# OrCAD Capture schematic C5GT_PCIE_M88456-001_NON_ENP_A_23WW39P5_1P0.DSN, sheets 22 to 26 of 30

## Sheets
22 PWR - Cycone V GT: size B
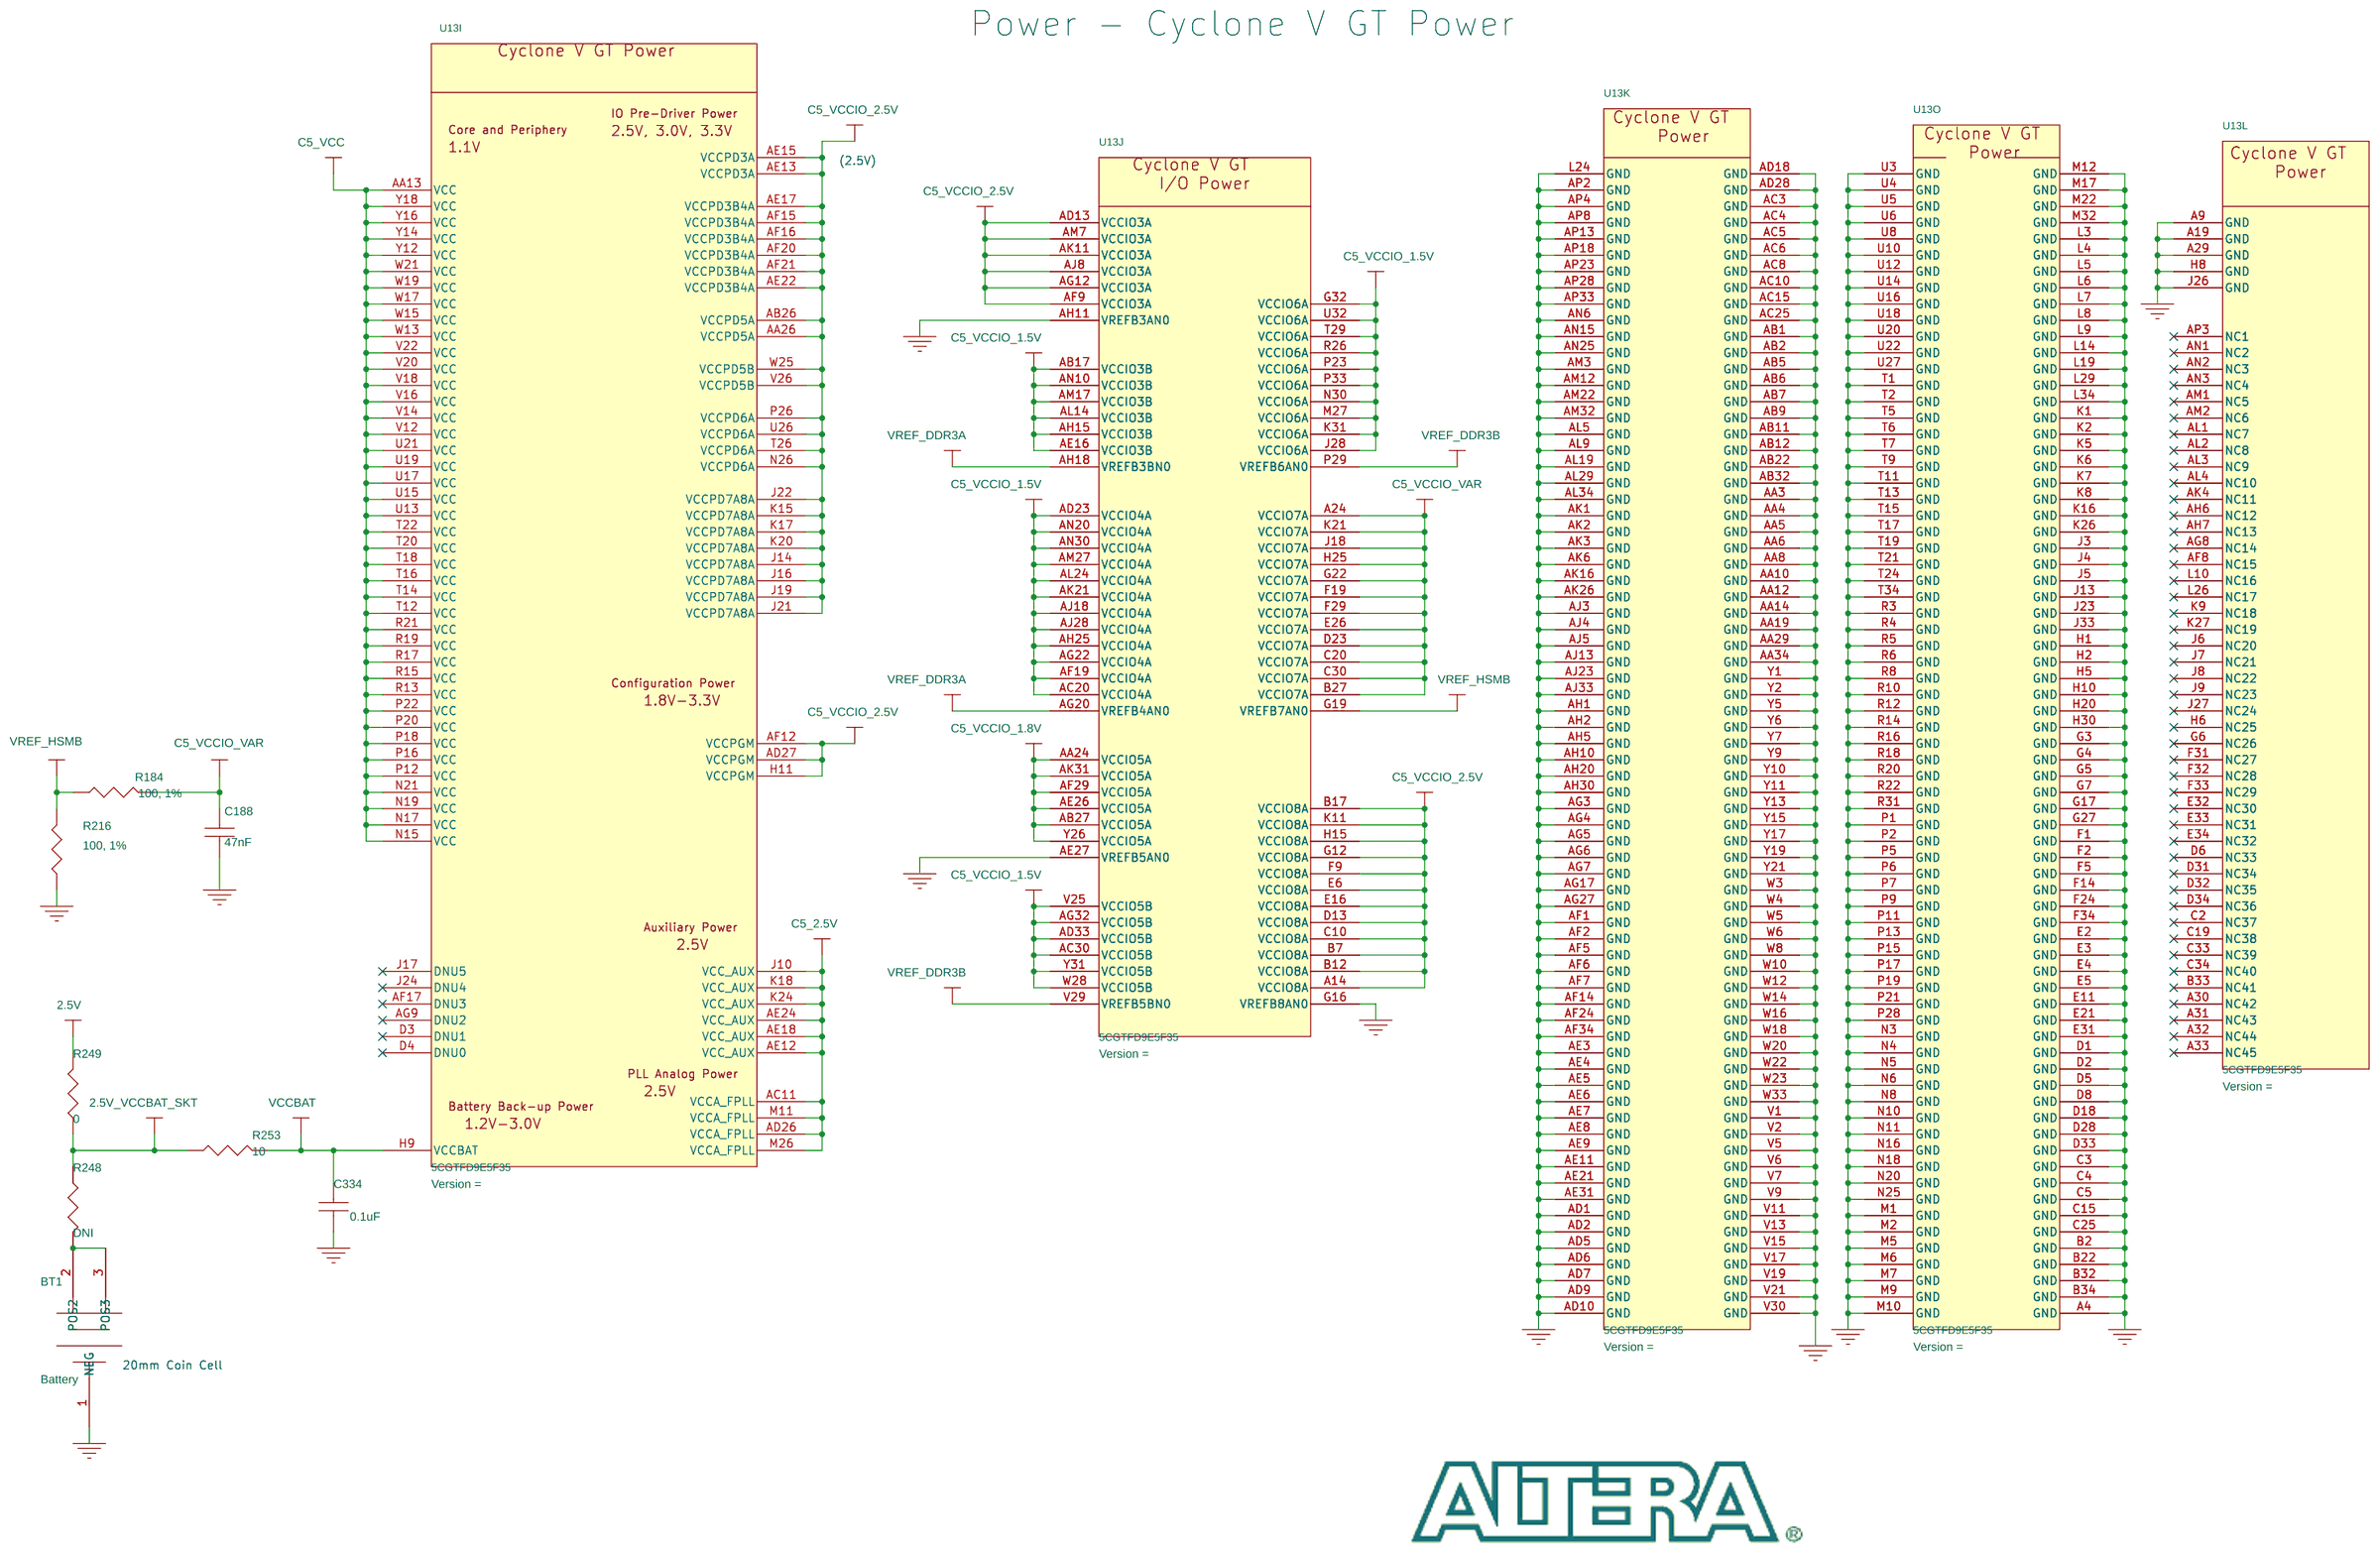
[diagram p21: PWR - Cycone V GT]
23 Power 1 - DCin to 12V,3.3V: size B
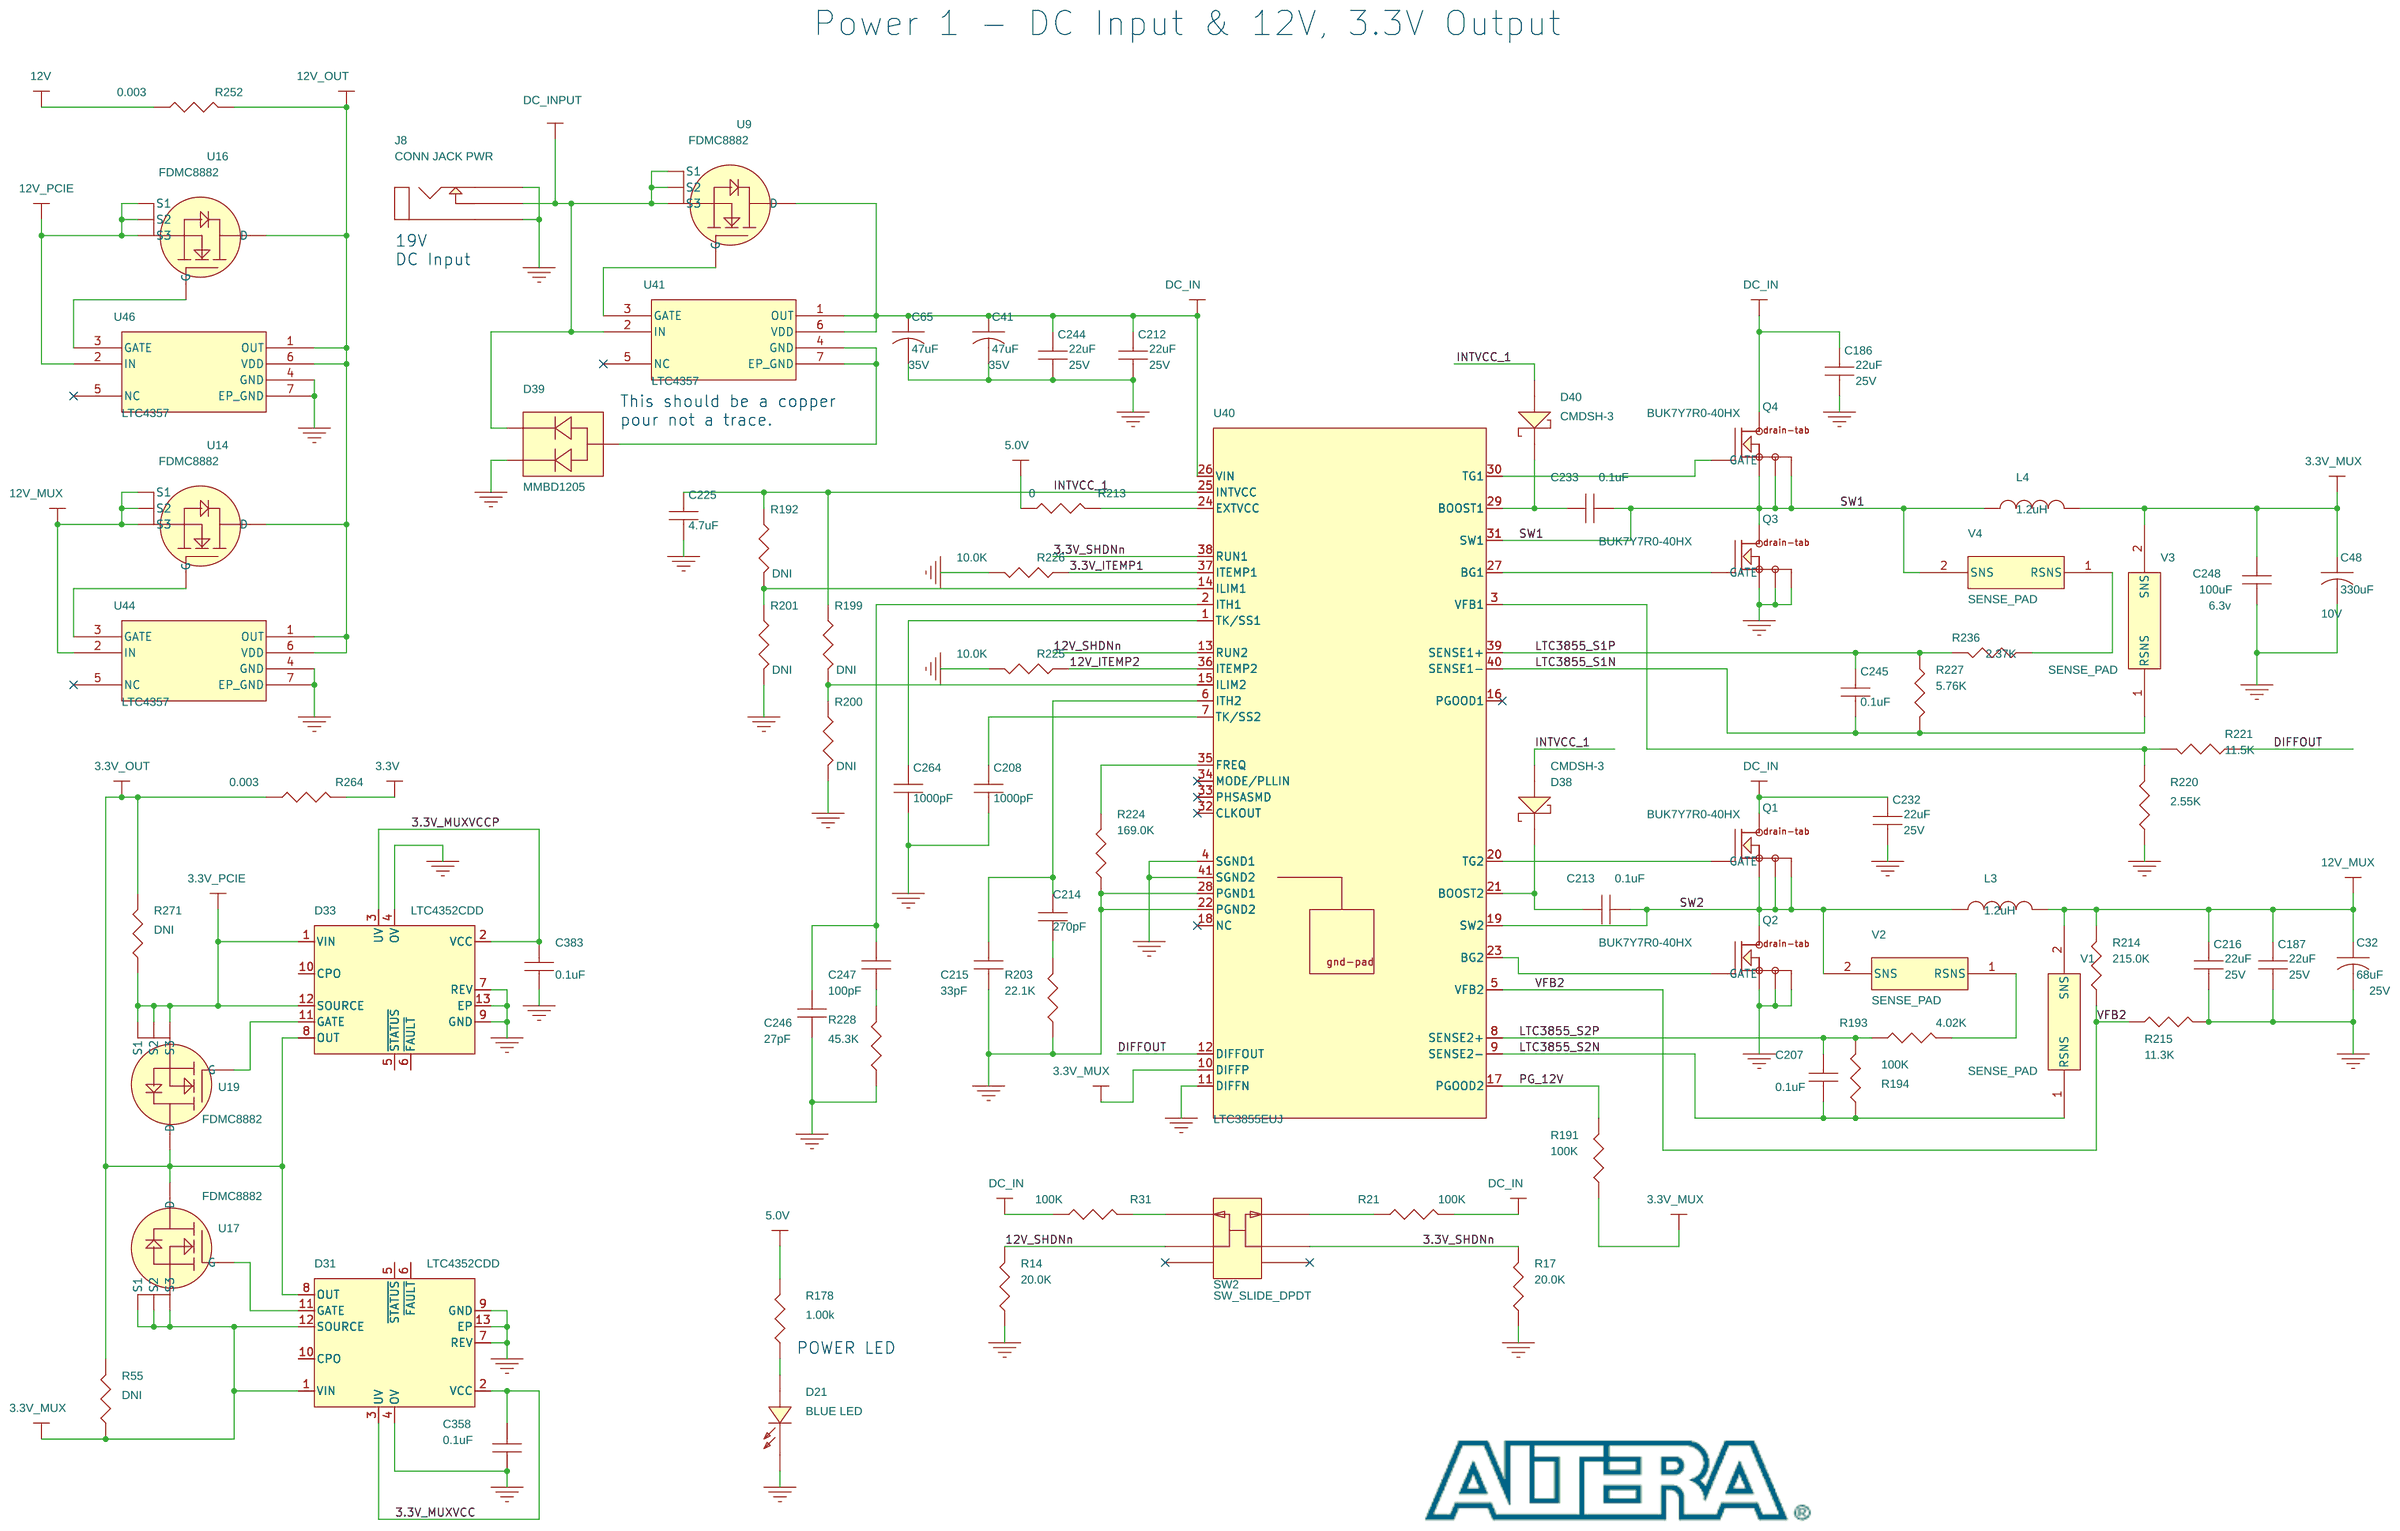
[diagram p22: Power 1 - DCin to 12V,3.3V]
24 Power 2 - 1.1V (C5_VCC): size B
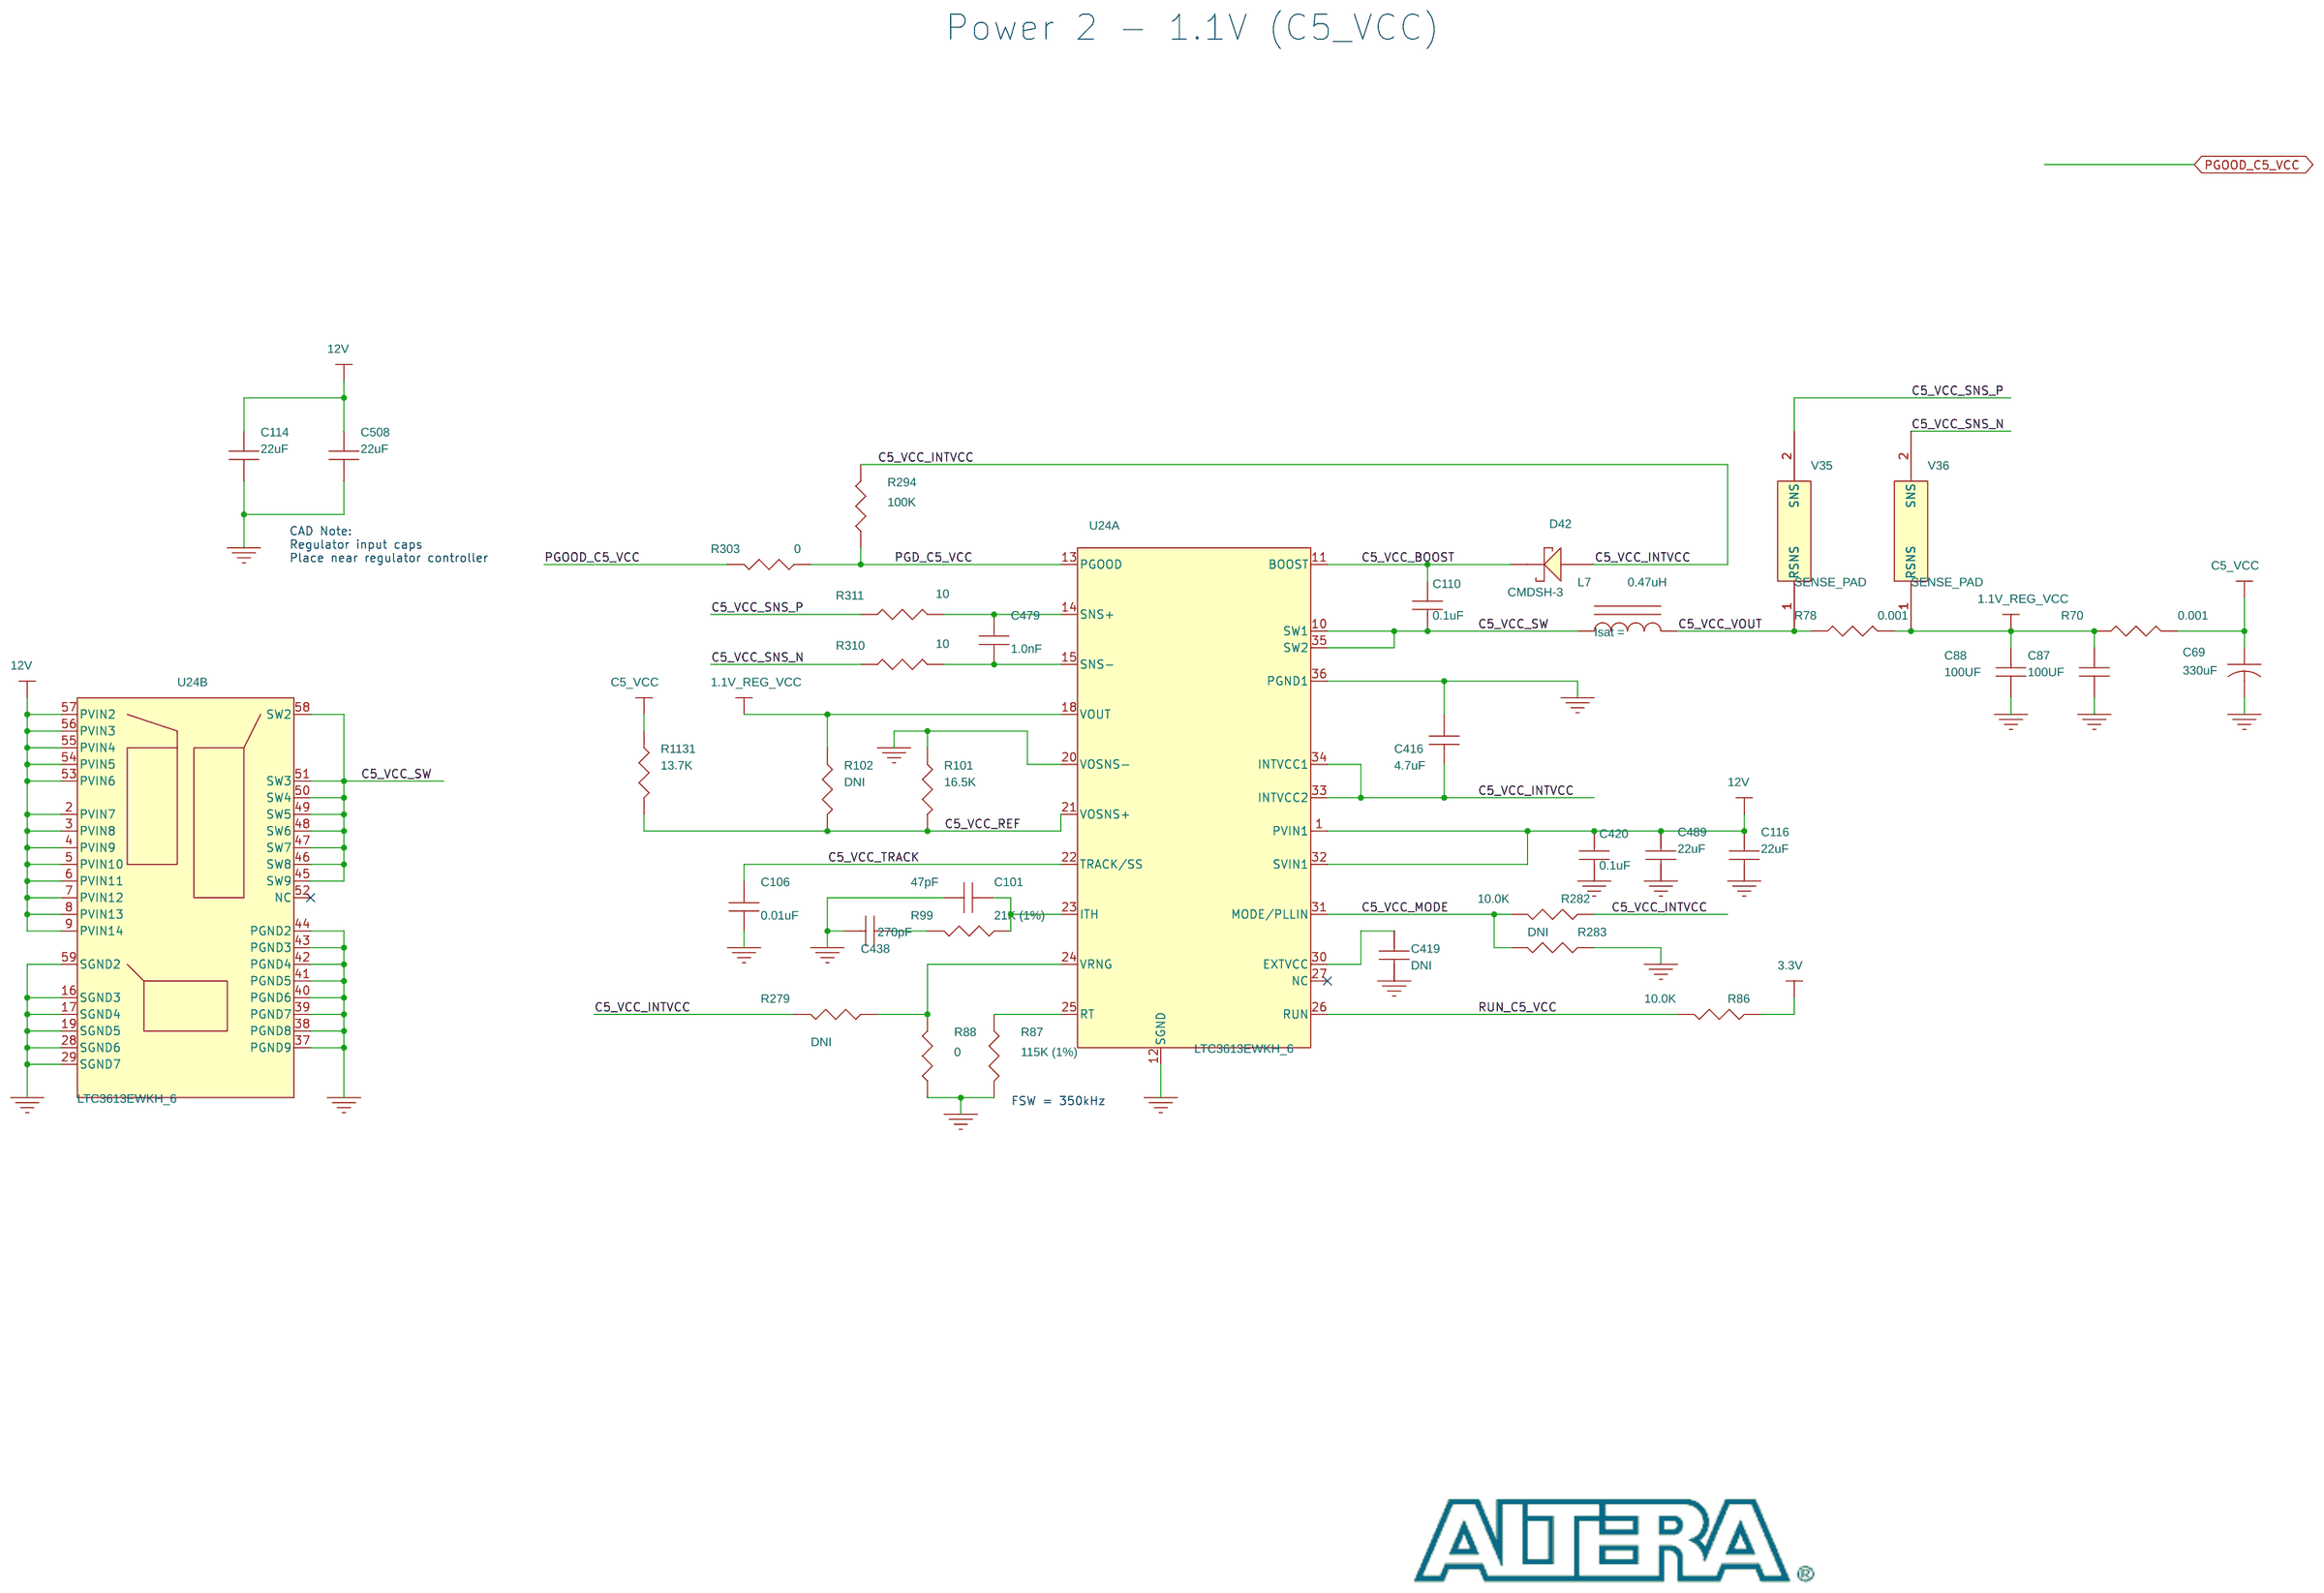
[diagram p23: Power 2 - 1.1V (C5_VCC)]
25 Power 3 - 1.2V (C5 GXB): size B
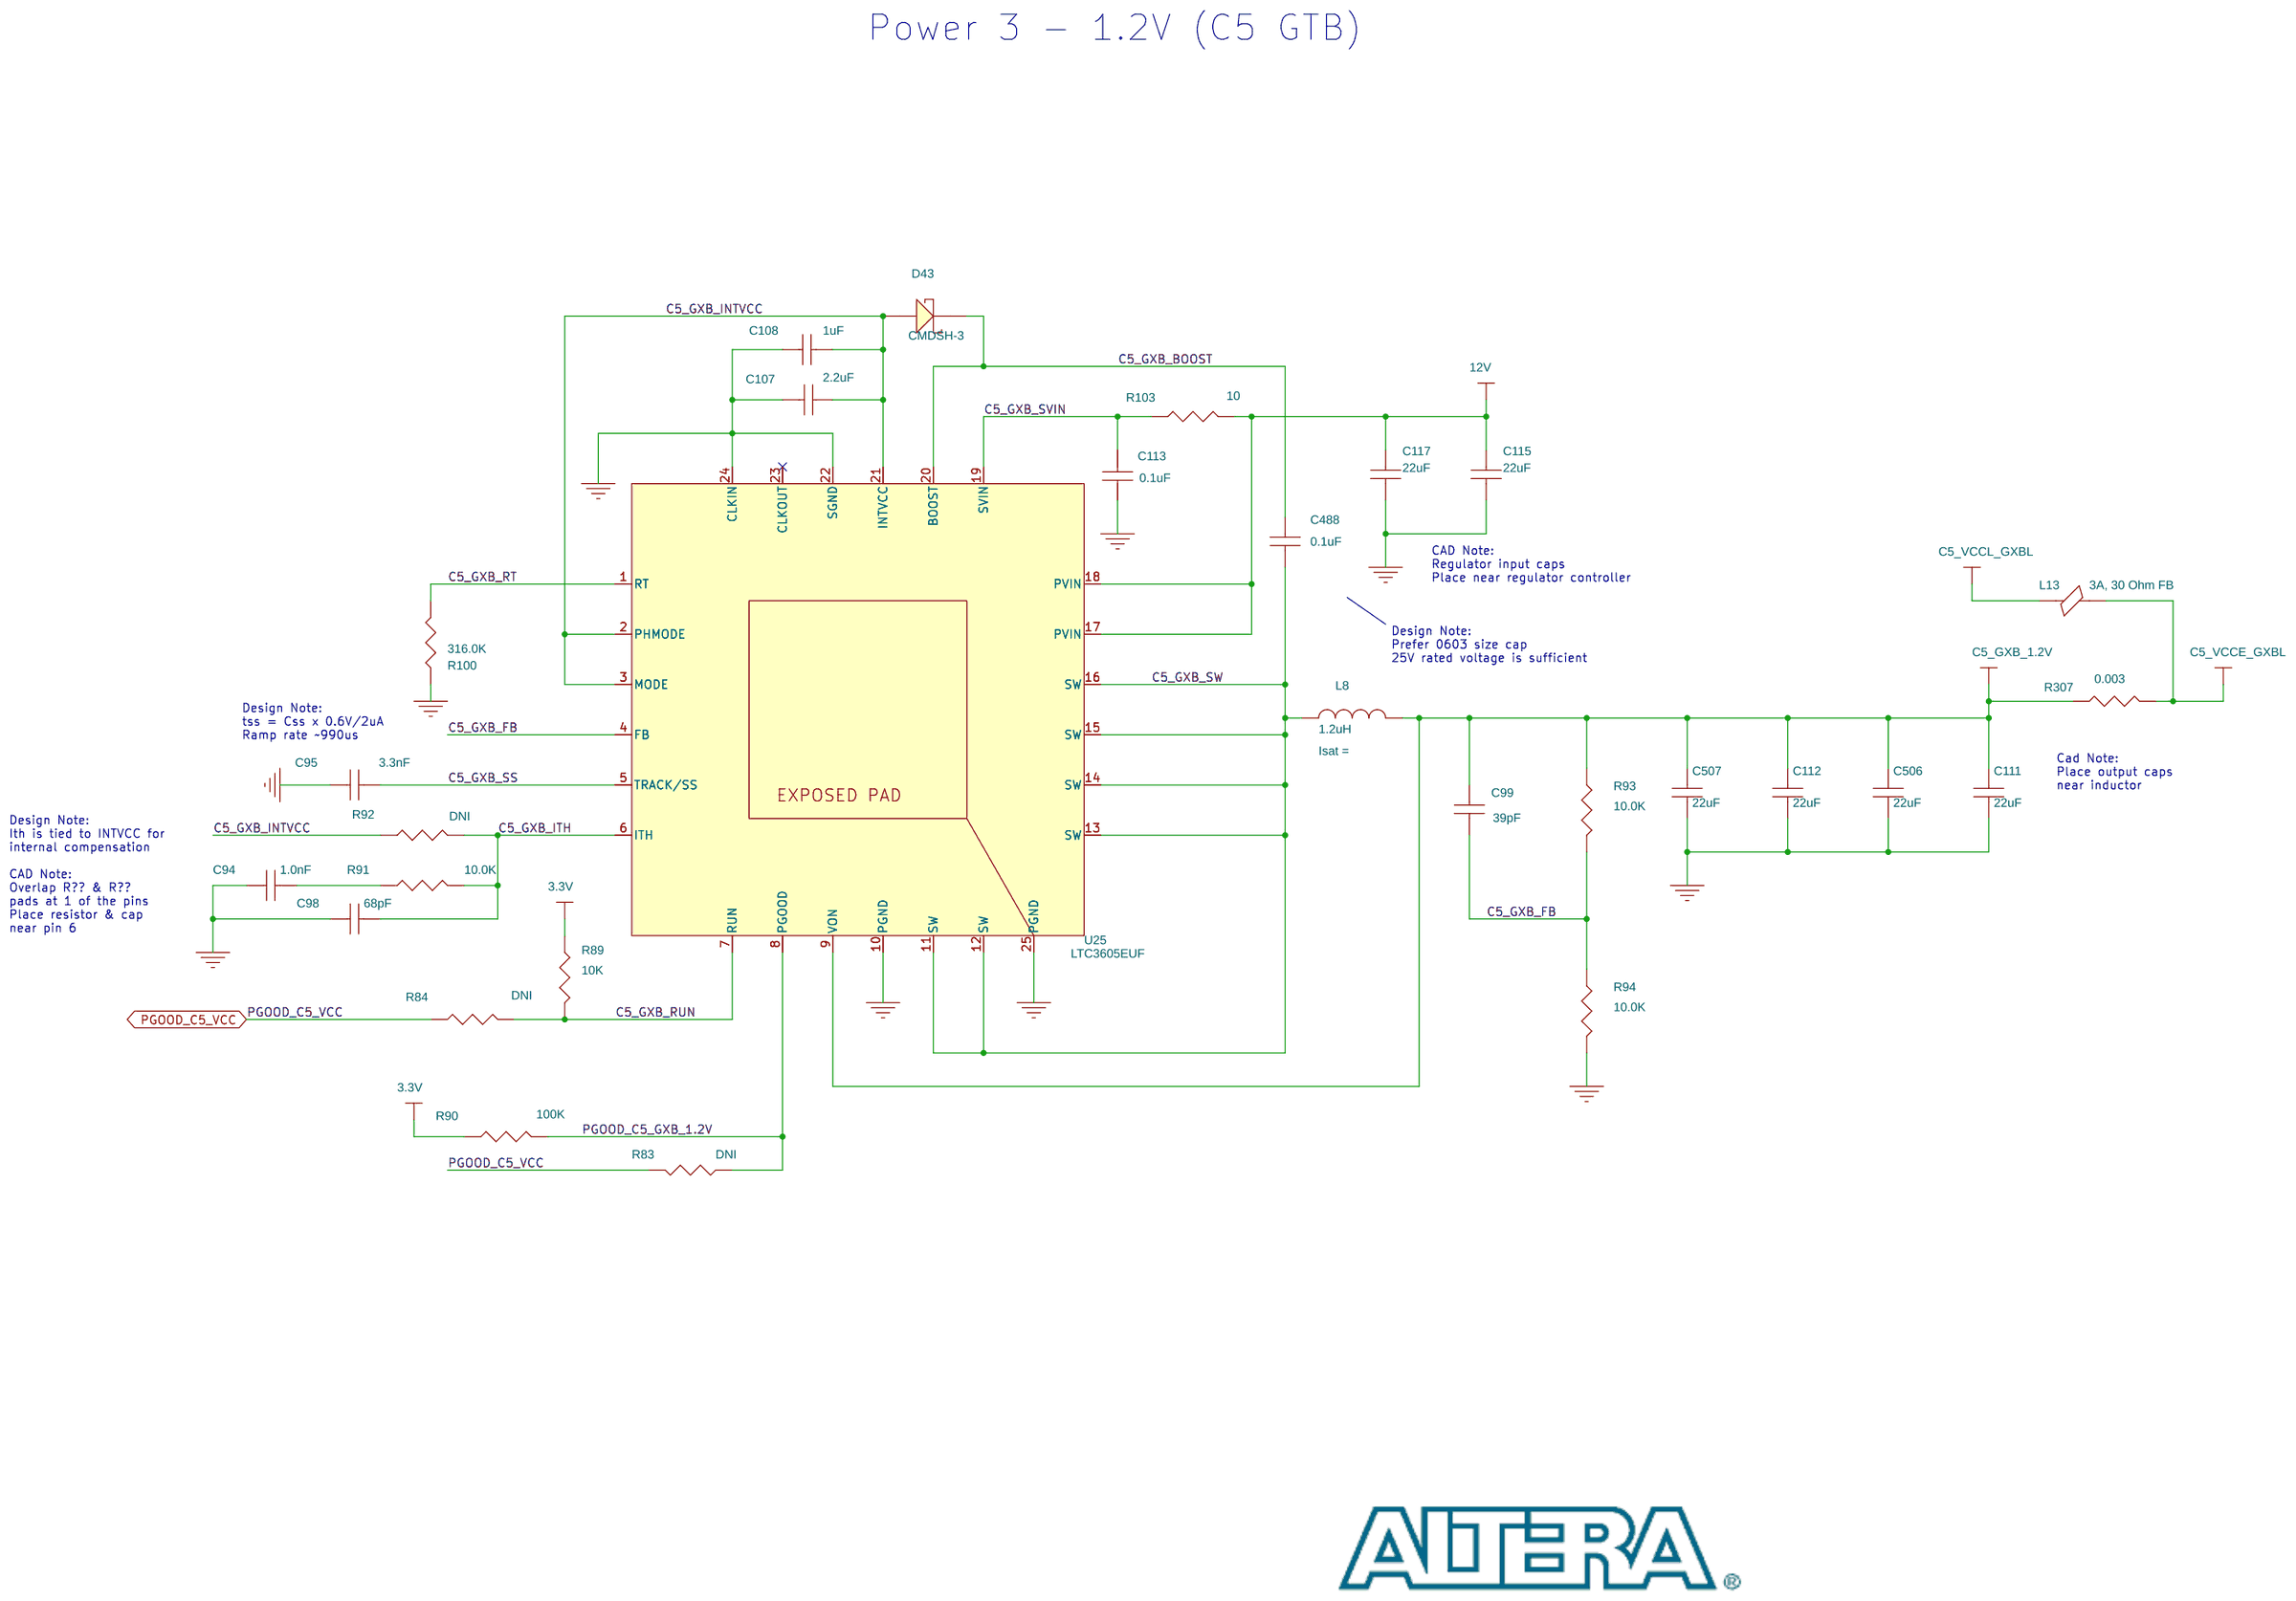
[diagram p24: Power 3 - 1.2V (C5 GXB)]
26 Power 4 - 2.5V (C5 2.5V): size B
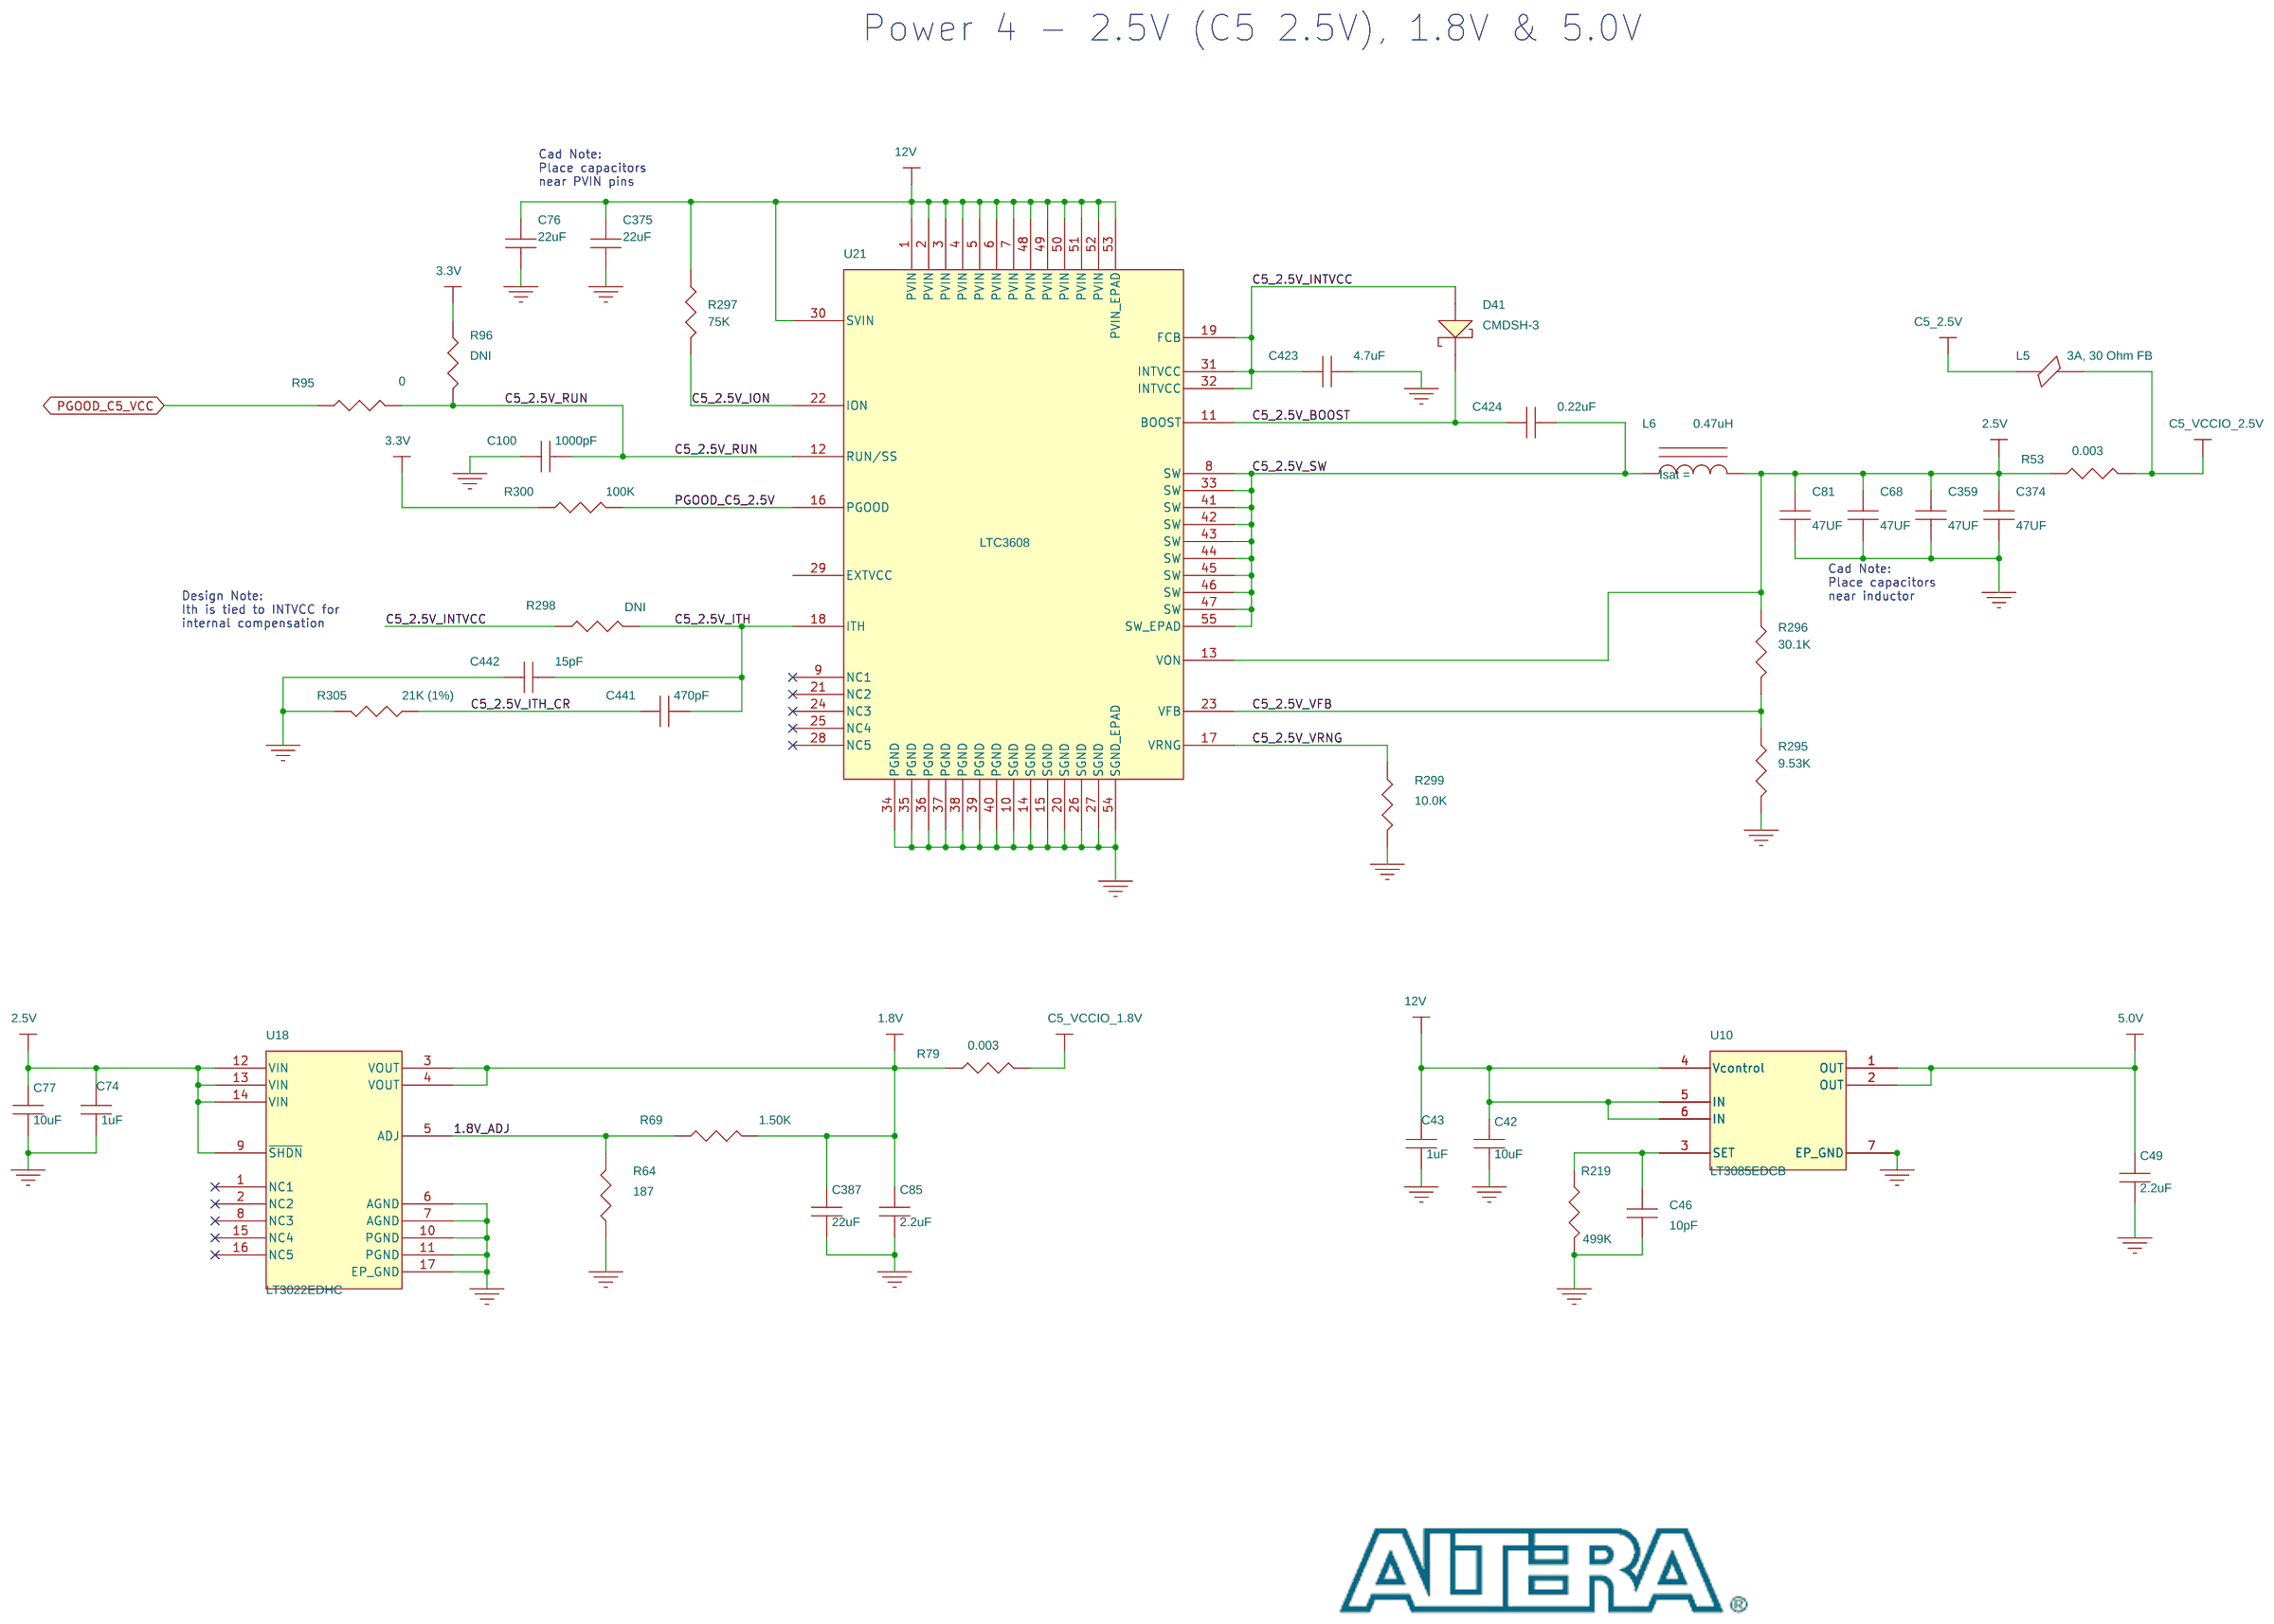
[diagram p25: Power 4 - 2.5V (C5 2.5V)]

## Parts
sheet Cyclone V GT,  XCVRs
U13  5CGTFD9E5F35  [F1152]  (sections A,B,C,D,E,F,G,H,I,J,K,L,M,N,O)
sheet Power 1 - DCin to 12V,3.3V
C32  68uF  [7343P]
C41  47uF  [7343-X]
C48  330uF  [7343p]
C65  47uF  [7343-X]
C186  22uF  [1210]
C187  22uF  [1210]
C207  0.1uF  [0402]
C208  1000pF  [0402]
C212  22uF  [1210]
C213  0.1uF  [0402]
C214  270pF  [0402]
C215  33pF  [0402]
C216  22uF  [1210]
C225  4.7uF  [0402]
C232  22uF  [1210]
C233  0.1uF  [0402]
C244  22uF  [1210]
C245  0.1uF  [0402]
C246  27pF  [0402]
C247  100pF  [0402]
C248  100uF  [1206]
C264  1000pF  [0402]
C358  0.1uF  [0603]
C383  0.1uF  [0603]
D21  BLUE LED  [LUMEX_LED0805]
D31  LTC4352CDD  [DFN12_EPAD]
D33  LTC4352CDD  [DFN12_EPAD]
D38  CMDSH-3  [SOD323]
D39  MMBD1205  [SOT23]
D40  CMDSH-3  [SOD323]
J8  CONN JACK PWR  [RAPC712]
L3  1.2uH  [IND_WURTH_744325120]
L4  1.2uH  [IND_WURTH_744325120]
Q1  BUK7Y7R0-40HX  [Lfpak-4]
Q2  BUK7Y7R0-40HX  [Lfpak-4]
Q3  BUK7Y7R0-40HX  [Lfpak-4]
Q4  BUK7Y7R0-40HX  [Lfpak-4]
R14  20.0K  [0402]
R17  20.0K  [0402]
R21  100K  [0402]
R31  100K  [0402]
R55  DNI  [0402]
R178  1.00k  [0402]
R191  100K  [0402]
R192  DNI  [0402]
R193  4.02K  [0402]
R194  100K  [0402]
R199  DNI  [0402]
R200  DNI  [0402]
R201  DNI  [0402]
R203  22.1K  [0402]
R213  0  [0402]
R214  215.0K  [0402]
R215  11.3K  [0402]
R220  2.55K  [0402]
R221  11.5K  [0402]
R224  169.0K  [0402]
R225  10.0K  [0402]
R226  10.0K  [0402]
R227  5.76K  [0402]
R228  45.3K  [0402]
R236  2.37K  [0402]
R252  0.003  [WSL2010]
R264  0.003  [WSL2010]
R271  DNI  [0402]
SW2  SW_SLIDE_DPDT  [EG2207]
U9  FDMC8882  [FDMC8878_VER2]
U14  FDMC8882  [FDMC8878_VER2]
U16  FDMC8882  [FDMC8878_VER2]
U17  FDMC8882  [FDMC8878_VER2]
U19  FDMC8882  [FDMC8878_VER2]
U40  LTC3855EUJ  [QFN40]
U41  LTC4357  [dfn6_epad]
U44  LTC4357  [dfn6_epad]
U46  LTC4357  [dfn6_epad]
V1  SENSE_PAD  [SENSE]
V2  SENSE_PAD  [SENSE]
V3  SENSE_PAD  [SENSE]
V4  SENSE_PAD  [SENSE]
sheet Power 2 - 1.1V (C5_VCC)
C69  330uF  [7343p]
C87  100UF  [1206]
C88  100UF  [1206]
C101  47pF  [0402]
C106  0.01uF  [0402]
C110  0.1uF  [0402]
C114  22uF  [1210]
C116  22uF  [1210]
C416  4.7uF  [0805]
C419  DNI  [0805]
C420  0.1uF  [0402]
C438  270pF  [0402]
C479  1.0nF  [0402]
C489  22uF  [1210]
C508  22uF  [1210]
D42  CMDSH-3  [SOD323]
L7  0.47uH  [ind_wurth_744314047]
R70  0.001  [1206]
R78  0.001  [WSL2010]
R86  10.0K  [0402]
R87  115K (1%)  [0402]
R88  0  [0402]
R99  21K (1%)  [0402]
R101  16.5K  [0402]
R102  DNI  [0402]
R279  DNI  [0402]
R282  10.0K  [0402]
R283  DNI  [0402]
R294  100K  [0402]
R303  0  [0402]
R310  10  [0402]
R311  10  [0402]
R1131  13.7K  [0402]
U24  LTC3613EWKH_6  [QFN56_7x9mm]  (sections A,B)
V35  SENSE_PAD  [SENSE]
V36  SENSE_PAD  [SENSE]
sheet Power 3 - 1.2V (C5 GXB)
C94  1.0nF  [0402]
C95  3.3nF  [0402]
C98  68pF  [0402]
C99  39pF  [0402]
C107  2.2uF  [0402]
C108  1uF  [0603]
C111  22uF  [0805]
C112  22uF  [0805]
C113  0.1uF  [0402]
C115  22uF  [1210]
C117  22uF  [1210]
C488  0.1uF  [0603]
C506  22uF  [0805]
C507  22uF  [0805]
D43  CMDSH-3  [SOD323]
L8  1.2uH  [IND_SUSUMU_PCMC_BTYPE]
L13  3A, 30 Ohm FB  [ind_0603]
R83  DNI  [0402]
R84  DNI  [0402]
R89  10K  [0402]
R90  100K  [0402]
R91  10.0K  [0402]
R92  DNI  [0402]
R93  10.0K  [0402]
R94  10.0K  [0402]
R100  316.0K  [0402]
R103  10  [0402]
R307  0.003  [WSL2010]
U25  LTC3605EUF  [qfn24]
sheet Power 4 - 2.5V (C5 2.5V)
C42  10uF  [0805]
C43  1uF  [0402]
C46  10pF  [0402]
C49  2.2uF  [0603]
C68  47UF  [1206]
C74  1uF  [0402]
C76  22uF  [1210]
C77  10uF  [0805]
C81  47UF  [1206]
C85  2.2uF  [0603]
C100  1000pF  [0402]
C359  47UF  [1206]
C374  47UF  [1206]
C375  22uF  [1210]
C387  22uF  [1210]
C423  4.7uF  [0805]
C424  0.22uF  [0402]
C441  470pF  [0402]
C442  15pF  [0402]
D41  CMDSH-3  [SOD323]
L5  3A, 30 Ohm FB  [ind_0603]
L6  0.47uH  [ind_wurth_744314047]
R53  0.003  [WSL2010]
R64  187  [0402]
R69  1.50K  [0402]
R79  0.003  [WSL2010]
R95  0  [0402]
R96  DNI  [0402]
R219  499K  [0402]
R295  9.53K  [0402]
R296  30.1K  [0402]
R297  75K  [0402]
R298  DNI  [0402]
R299  10.0K  [0402]
R300  100K  [0402]
R305  21K (1%)  [0402]
U10  LT3085EDCB  [dfn6-3x2_epad]
U18  LT3022EDHC  [dfn16_epad_5x3]
U21  LTC3608  [qfn52_3epad]
sheet PWR - Cycone V GT
BT1  Battery  [Keystone_bt-2994]
C188  47nF  [0402]
C334  0.1uF  [0402]
R184  100, 1%  [0402]
R216  100, 1%  [0402]
R248  DNI  [0402]
R249  0  [0402]
R253  10  [0402]

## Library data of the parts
U13 = 5CGTFD9E5F35: IC - FPGA, Cyclone V GT F1152, 301K LEs, (35x35)mm BGA, leadfree; Created by: pmurray; Date: 10/29/12; IPN: 965959; Item Num: P01-17810R; Manufacturer: Altera; Manufacturer Part Num: 5CGTFD9E5F35C7N
C32 = PCAP: CAP - 68UF 25V 7343 10%; IPN: K16344-001; Item Num: P03-15042R; LIFECYCLE_PHASE: Active; Lead Free Status: Lead Free; MFR_LIFECYCLE: Active; Manufacturer: Kemet Corporation; Manufacturer Part Num: T495X686K025ATE200; Num Pins: 2; PART_SUBCLASS: CAPACITORS; RATED_VOLTAGE: 25V; RoHS Compliant: RoHS Compliant; TOLERANCE: +/-10%
C41 C65 = PCAP: CAP - POLY TANT, 47UF, 35V, 20%, ESR 0.070 OHM, SMD 7343-43; AGILE_LINK: http://sj-agile9app/Agile/PLMServlet?action=OpenEmailObject&classid=10000&objid=262610020; IPN: K21324-001; Item Num: P03-17552R; LIFECYCLE_PHASE: Preliminary; Lead Free Status: Lead Free; MFR_LIFECYCLE: Active; Manufacturer: Kemet Corporation; Manufacturer Part Num: T521X476M035AHE070; Num Pins: 2; PART_SUBCLASS: CAPACITORS; RATED_VOLTAGE: 35V; RoHS Compliant: RoHS Compliant; TOLERANCE: +/-20%
C48 = PCAP: CAP - TANT, 330UF, 10V, 20%, SMD; AGILE_LINK: http://sj-agile9app/Agile/PLMServlet?action=OpenEmailObject&classid=10000&objid=257237054; IPN: K16359-001; Item Num: P03-15278R; LIFECYCLE_PHASE: Active; Lead Free Status: Lead Free; MFR_LIFECYCLE: Active; Manufacturer: AVX Corp; Manufacturer Part Num: TPME337M010R0023; Num Pins: 2; PART_SUBCLASS: CAPACITORS; RATED_VOLTAGE: 10V; RoHS Compliant: RoHS Compliant; TOLERANCE: +/-20%
C186 C187 C212 C216 C232 C244 = CAP: CAP - CER, 22UF, 25V, X7R, 1210, SMD; IPN: G38032-001; Item Num: P03-17454R; LIFECYCLE_PHASE: Active; Lead Free Status: Lead Free; MFR_LIFECYCLE: Active; Manufacturer: Murata; Manufacturer Part Num: GRM32ER71E226KE15L; Num Pins: 2; PART_SUBCLASS: CAPACITORS; RATED_VOLTAGE: 25V; RoHS Compliant: RoHS Compliant; TOLERANCE: +/-10%
C207 C213 C233 C245 = CAP: CAP, CER .1UF 16V X7R 0402; AGILE_LINK: http://sj-agile9app/Agile/PLMServlet?action=OpenEmailObject&classid=10000&objid=242850580; IPN: A36096-030; Item Num: P03-15136R; LIFECYCLE_PHASE: Active; Lead Free Status: Lead Free; MFR_LIFECYCLE: Active; Manufacturer: Murata; Manufacturer Part Num: GRM155R71C104KA88D; Num Pins: 2; PACKAGING: Tape & Reel (TR); PART_SUBCLASS: CAPACITORS; Part Class: CAPACITORS; RATED_VOLTAGE: 16V; RoHS Compliant: RoHS Compliant; TOLERANCE: +/-10%
C208 C264 = CAP: CAP - CERAMIC, 1000PF 50V 10% X7R 0402; AGILE_LINK: http://sj-agile9app/Agile/PLMServlet?action=OpenEmailObject&classid=10000&objid=213459014; IPN: A36096-004; Item Num: P03-15056R; LIFECYCLE_PHASE: Active; Lead Free Status: Lead Free; MFR_LIFECYCLE: Active; Manufacturer: Murata; Manufacturer Part Num: GRM155R71H102K; Num Pins: 2; PART_SUBCLASS: CAPACITORS; RATED_VOLTAGE: 50V; RoHS Compliant: RoHS Compliant; TOLERANCE: +/-10%
C214 C438 = CAP: CAP - CERAMIC, 270PF 0402 50V 5% C0G; IPN: D70542-107; Item Num: P03-15059R; Lead Free Status: No; Manufacturer: Murata; Manufacturer Part Num: GRM1555C1H271JA01D; Num Pins: 2; Part Class: CAPACITORS; Price: 0; RoHS Compliant: Yes
C215 = CAP: CAP - CER, 33PF, 5%, 0402, 50VDC, C0G; IPN: K13772-001; Item Num: P03-15572R; Manufacturer: Murata; Manufacturer Part Num: GRM1555C1H330JZ01D; Num Pins: 2; PART_SUBCLASS: CAPACITORS; RATED_VOLTAGE: 50V; TOLERANCE: 5%; Working Voltage: 50V
C225 = CAP: CAP - CERAMIC, 4.7UF, 6.3V, 10%, X5R, 0402; AGILE_LINK: http://sj-agile9app/Agile/PLMServlet?action=OpenEmailObject&classid=10000&objid=257560276; IPN: A36096-107; Item Num: P03-17432R; LIFECYCLE_PHASE: Active; Lead Free Status: Not Lead Free; MFR_LIFECYCLE: Active; Manufacturer: Murata; Manufacturer Part Num: GRM155R60J475ME87D; Num Pins: 2; PART_SUBCLASS: CAPACITORS; RATED_VOLTAGE: 6.3V; RoHS Compliant: RoHS Compliant; TOLERANCE: +/-10%
C246 = CAP: CAP, CERAMIC, 27PF, 5%, 50V, 0402, NPO; IPN: K13764-001; Item Num: P03-15552R; Manufacturer: Panasonic; Manufacturer Part Num: ECJ-0EC1H270J; Num Pins: 2; PART_SUBCLASS: CAPACITORS
C247 = CAP: CAP, CERAMIC, 100PF, 10%, 50V, 0402, X7R; AGILE_LINK: http://sj-agile9app/Agile/PLMServlet?action=OpenEmailObject&classid=10000&objid=242850580; CAPACITANCE: 47pF; IPN: K19395-001; Item Num: P03-15133R; Manufacturer: Panasonic; Manufacturer Part Num: ECJ-0EB1H101K; Num Pins: 2; PART_SUBCLASS: CAPACITORS
C248 = CAP: CAP - CER 100UF 6.3V X5R 1206; Dielectric: X5R; IPN: 108426-196; Item Num: P03-15292R; Manufacturer: Murata; Manufacturer Part Num: GRM31CR60J107ME39L; RATED_VOLTAGE: 6.3v; RoHS Compliant: Yes; Tolerance: 20%; Working Voltage: 6.3V
C358 C383 = CAP: CAP - CERAMIC 0.1UF 50V Y5V 0603; Dielectric: Y5V; IPN: M31986-001; Item Num: P03-15119R; LIFECYCLE_PHASE: Active; Lead Free Status: Lead Free; Manufacturer: Panasonic; Manufacturer Part Num: C0603C104K5REC; Num Pins: 2; Part Class: CAPACITORS; RoHS Compliant: RoHS Compliant
D21 = LED: LED - BLUE, VF=3.5V, 0805 SMD; IPN: K15369-001; Item Num: P09-21321R; Lead Free Status: No; Manufacturer: Lumex; Manufacturer Part Num: SML-LX0805USBC-TR; Num Pins: 2; Part Class: LEDS; RoHS Compliant: Yes
D31 D33 = LTC4352CDD: DIODE - LOW VOLTAGE IDEAL DIODE CONTROLLER W/ MONITORING , 2.9V - 18V, 5US, 3X3MM DFN12; IPN: K12737-001; Item Num: P08-20277R; Manufacturer: Linear Technology; Manufacturer Part Num: LTC4352CDD#PBF
D38 D40 = D-SCHOTTKY_0: DIODE,CMDSH-3 SOD323; IPN: A81685-001; Item Num: P08-20717R; Manufacturer: Central Semiconductor; Part Number: CENTRAL CMDSH-3TR
D39 = MMBD1205: DIODE - ULT FAST, 100V, 200MA, SOT-23; IPN: K12738-001; Item Num: P08-20797R; Manufacturer: Fairchild Semiconductor
J8 = CONN_JACK_PWR_3: CONN, DC Power Jack, RAPC712, R/A, 3 Pins; IPN: E58104-001; Item Num: P23-35030R; Manufacturer: Switchcraft; Manufacturer Part Num: RAPC712X
L3 L4 = INDUCTOR: IND - 1.2UH, POWER IND, 20A, SMD (10.5 X 10.2)MM; IPN: K14469-001; Item Num: P04-17096R; LIFECYCLE_PHASE: Preliminary; Lead Free Status: Lead Free; MFR_LIFECYCLE: Active; Manufacturer: Wurth Elektronik; Manufacturer Part Num: 744325120; Num Pins: 2; PART_SUBCLASS: INDUCTORS; RoHS Compliant: RoHS Compliant
Q1 Q4 = rjk0301dpb: XSTR, N-CHANNEL MOSFET, RJK0305DPB; IPN: N19110-001; Manufacturer: Renesas Technology Corp.; item Num: P18-31395R
Q2 Q3 = rjk0301dpb: MOSFET, N-CHANNEL, 60A, LFPAK, RJK0301DPB; IPN: N19110-001; Manufacturer: Renesas Technology Corp.; item Num: P18-31396R
R14 R17 = RESISTOR: RES 20.0K OHM 1/16W 1% 0402 SMD; IPN: A93548-181; Item Num: P02-14071R; Lead Free Status: Yes; Manufacturer: Panasonic; Manufacturer Part Num: ERJ-2RKF2002X; Num Pins: 2; Part Class: RESISTORS; RoHS Compliant: Yes
R21 R31 R191 = RESISTOR: RES,100K OHMS,1.0%,1/16W,0402; IPN: A93548-596; Item Num: P02-11386R; Lead Free Status: No; Manufacturer: Panasonic; Manufacturer Part Num: ERJ-2RKF1003X; Num Pins: 2; Part Class: Resistors; Price: 0; RoHS Compliant: Yes
R55 R271 = RESISTOR: RES ZERO OHM 1/16W 5% 0402 SMD; IPN: A93549-001; Item Num: P02-14020R; Lead Free Status: No; Manufacturer: Panasonic; Manufacturer Part Num: ERJ-2GE0R00X; Num Pins: 2; Part Class: Resistors; Price: 0; RoHS Compliant: Yes
R178 = RESISTOR: RES,1.00K OHMS,1.0%,1/16W,0402; IPN: G60609-021; Item Num: P02-11372R; Lead Free Status: No; Manufacturer: Panasonic; Manufacturer Part Num: ERJ-2RKF1001X; Num Pins: 2; Part Class: Resistors
R192 R199-R201 = RESISTOR: RES ZERO OHM 1/16W 5% 0402 SMD; AGILE_LINK: http://sj-agile9app/Agile/PLMServlet?action=OpenEmailObject&classid=10000&objid=188481525; IPN: A93549-001; Item Num: P02-14020R; LIFECYCLE_PHASE: Active; MFR_LIFECYCLE: Active; Manufacturer: Panasonic; Manufacturer Part Num: ERJ-2GE0R00X; Num Pins: 2; PART_SUBCLASS: RESISTORS; POWER: 1/16W; RESISTANCE: 0; RoHS Compliant: RoHS Compliant; TOLERANCE: +/-5%
R193 = RESISTOR: RES - 4.02K OHM, 1/16W, 1%, 0402 SMD; IPN: K15726-001; Item Num: P02-15351R; LIFECYCLE_PHASE: Active; MFR_LIFECYCLE: Active; Manufacturer: Panasonic; Manufacturer Part Num: ERJ-2RKF4021x; Num Pins: 2; PART_SUBCLASS: RESISTORS; POWER: 1/16W; RoHS Compliant: RoHS Compliant; TOLERANCE: +/-1%
R194 = RESISTOR: RES,100K OHMS,1.0%,1/16W,0402; IPN: A93548-596; Item Num: P02-11386R; Lead Free Status: Yes; Manufacturer: Panasonic; Manufacturer Part Num: ERJ-2RKF1003X; Num Pins: 2; Part Class: Resistors; Price: 0; RoHS Compliant: Yes
R203 = RESISTOR: RES - 22.1KOHM, 1/16W, 1%, 0402 SMD; IPN: A93548-147; Item Num: P02-14447R; Manufacturer: Vishay; Manufacturer Part Num: CRCW040222K1FKED
R83 R84 R88 R92 R95 R213 R248 R249 R279 R283 R298 R303 = RES_0_OHM_5%_1_16W_0402_SMD: IPN: A93549-001
R214 = RESISTOR: RES - 215.0K OHM, 1/16W, 1%, 0402 SMD; IPN: A93548-405; Manufacturer: Vishay; Manufacturer Part Num: CRCW0402215KFKED; item Num: P02-17248R
R215 = RESISTOR: RES - 11.3K OHM, 1/16W, 1%, 0402 SMD; IPN: K15739-001; Manufacturer: Vishay; Manufacturer Part Num: CRCW040211K3FKED; item Num: P02-17249R
R220 = RESISTOR: RES - 2.55K OHM, 1/16W, 1%, 0402 SMD; IPN: A93548-241; Manufacturer: Vishay; Manufacturer Part Num: CRCW04022K55FKED; item Num: P02-16112R
R221 = RESISTOR: RES - 11.5K OHM 1/16W 1% 0402 SMD; IPN: K21584-001; Manufacturer: Panasonic; Manufacturer Part Num: ERJ-2RKF1152X; item Num: P02-14073R
R224 = RESISTOR: RES 169K OHM 1/16W 1% 0402 SMD; IPN: A93548-290; Item Num: P02-17210R; Manufacturer: Vishay; Manufacturer Part Num: CRCW0402169KFKED
R86 R225 R226 R282 = RESISTOR: RES,10.0K OHMS,1.0%,1/16W, 0402; AGILE_LINK: http://sj-agile9app/Agile/PLMServlet?action=OpenEmailObject&classid=10000&objid=146548997; IPN: A93548-034; Item Num: P02-11364R; LIFECYCLE_PHASE: Active; Manufacturer: Panasonic; Manufacturer Part Num: ERJ-2RKF1002X; Num Pins: 2; PART_SUBCLASS: RESISTORS; POWER: 1/16W; RESISTANCE: 10K; TOLERANCE: +/-1%
R227 = RESISTOR: RES - 5.76K OHM, 1/16W, 1%, 0402 SMD; IPN: K15735-001; Item Num: P02-15108R; Lead Free Status: Yes; Manufacturer: Panasonic; Manufacturer Part Num: ERJ-2RKF5761X; Num Pins: 2; Part Class: Resistors; Price: 0; RoHS Compliant: Yes
R228 = RESISTOR: RES - 45.3K OHM, 1/10W, 1%, 0402 SMD; IPN: H80387-001; Item Num: P02-17524R; Manufacturer: Panasonic; Manufacturer Part Num: ERJ-2RKF4532X
R236 = RESISTOR: RES 2.37K OHM 1/16W 1% 0402 SMD; IPN: K15762-001; Item Num: P02-17209R; Manufacturer: Vishay; Manufacturer Part Num: CRCW04022K37FKED
R252 R264 = RESISTOR: RES, 0.003 OHM, 1%, 1/2W, POWERMETAL; IPN: C14411-035; Item Num: P02-10702R; Lead Free Status: Yes; Manufacturer: Vishay; Manufacturer Part Num: WSL20103L000FEA; Num Pins: 2; Part Class: Resistors; Price: 0; RoHS Compliant: Yes
SW2 = SW_SLIDE_DPDT: SWITCH - SLIDE DPDT, 30V, 0.2AMP, Vertical; IPN: J42686-001; Item Num: P11-24518R; Manufacturer: E-SWITCH
U9 U14 U16 U17 U19 = FDMC8878_VER2: MOSFET - N-CHANNEL Pwr Trench 16.5A 30V 14MOHM Power33; IPN: K14503-002; Item Num: P18-31175R; Manufacturer: Fairchild Semiconductor
U40 = LTC3855: SWITCHING REG,DUAL, MULTIPHASE, DC/DC WITH REMOTE SENSE, LTC3855, QFN-40; IPN: K13815-001; Item Num: P01-17346R; Manufacturer: Linear Technology; Manufacturer Part Num: LTC3855EUJ#PBF; Part Class: IC
U41 U44 U46 = LTC4357: IC - POSITIVE HIGH VOLTAGE IDEAL DIODE CONTROLLER, VIN 9V-80V, 6-LEAD DFN; AGILE_LINK: http://sj-agile9app/Agile/PLMServlet?action=OpenEmailObject&classid=10000&objid=259478351; IPN: K13832-001; Item Num: P01-14904R; LIFECYCLE_PHASE: Preliminary; Lead Free Status: Lead Free; MFR_LIFECYCLE: Active; Manufacturer: Linear Technology; Manufacturer Part Num: LTC4357IDCB#xxxPBF; Num Pins: 7; PART_SUBCLASS: ICS; RoHS Compliant: RoHS Compliant
V1-V4 V35 V36 = SENSE_PAD: IPN: #N/A
C69 = CAP-TANT_330UF_7343_20%_6.3V: IPN: 724613-042
C87 C88 = Cap_100UF_+_-20%_6.3V_1206: IPN: 108426-196
C101 = CAP: CAP, CERAMIC, 47PF, 0402, 5%, 50VDC, NPO; AGILE_LINK: http://sj-agile9app/Agile/PLMServlet?action=OpenEmailObject&classid=10000&objid=242850580; IPN: D17310-001; Item Num: P03-11678R; Manufacturer: Panasonic; Manufacturer Part Num: ECJ-0EC1H470J; Num Pins: 2; PART_SUBCLASS: CAPACITORS
C106 = CAP: CAP,CER,0.01uF,0402,10%,25VD; IPN: A36096-045; Item Num: P03-11343R; Lead Free Status: No; Manufacturer: Panasonic; Manufacturer Part Num: ECJ-0EB1E103K; Num Pins: 2; Part Class: CAPACITORS; Price: 0; RoHS Compliant: Yes
C110 C334 C420 = CAP: CAP - CERAMIC,  0.1UF 0402 25VDC Y5V; Dielectric: X5R; IPN: K13560-001; Item Num: P03-15057R; Lead Free Status: Yes; Manufacturer: Murata; Manufacturer Part Num: GRM155F51E104ZA01D; Manufacturer's Part No.: GRM155F51E104ZA01D; Num Pins: 2; Part Class: CAPACITORS; Price: 0.07; RoHS Compliant: Yes; Tolerance: 10%
C76 C114-C117 C375 C489 C508 = CAP_22uF_+_-10%_25V_1210: IPN: G38032-001
C416 = CAP: CAP - CERAMIC, 4.7UF, 10%, 16V, 0805, X5R; IPN: M97318-001; Item Num: P03-15097R; Lead Free Status: Yes; Manufacturer: Panasonic; Manufacturer Part Num: ECJ-2FB1C475K; Num Pins: 2; Part Class: Capacitors; Price: 0; RoHS Compliant: Yes
C419 = CAPACITOR_NON-POL: CAP - CERAMIC 1uF 16v X7R; IPN: #N/A; Item Num: P03-15257R; Lead Free Status: Yes; Manufacturer: Murata; Manufacturer Part Num: GRM21BR71C105KA01; Num Pins: 2; Part Class: Capacitors; Price: 0; RoHS Compliant: Yes
C94 C479 = CAP: CAP - CER, 1NF, 10%, 50V, X7R, 0402; AGILE_LINK: http://sj-agile9app/Agile/PLMServlet?action=OpenEmailObject&classid=10000&objid=256956561; IPN: D62711-001; Item Num: P03-15174R; LIFECYCLE_PHASE: Active; MFR_LIFECYCLE: Active; Manufacturer: Murata; Manufacturer Part Num: GRM155R71H102KA01D; Num Pins: 2; PART_SUBCLASS: CAPACITORS; RATED_VOLTAGE: 50V; RoHS Compliant: RoHS Compliant; TOLERANCE: +/-10%
D41-D43 = DIODE,_SCHOTTKY_CMDSH-3: IPN: A81685-001
L6 L7 = IND_0.47uH_Ir=18A_Isat=20A_SMD: IPN: K14466-001
R70 = RES_0.001_OHM_1%_1W_2010: RES - 0.001 OHM, 1W, 1%, 1206 SMD; IPN: J35342-001; Item Num: P02-17531R; Manufacturer: Stackpole Electronics Inc; Manufacturer Part Num: CSNL1206FT1L00
R78 = RESISTOR: 0.001 1% 1WATT SENSE RESISTOR 2010 CASE; AGILE_LINK: http://sj-agile9app/Agile/PLMServlet?action=OpenEmailObject&classid=10000&objid=260822062; IPN: E30969-002; Item Num: P02-16379R; LIFECYCLE_PHASE: Active; MFR_LIFECYCLE: Active; Manufacturer: Vishay; Manufacturer Part Num: WSL20101L000FEA18; Num Pins: 2; PART_SUBCLASS: RESISTORS; RoHS Compliant: RoHS Compliant
R87 = RESISTOR_0402: RES - 115K OHM 1/16W 1% 0402 SMD; AGILE_LINK: http://sj-agile9app/Agile/PLMServlet?action=OpenEmailObject&classid=10000&objid=197674503; IPN: K15855-001; Item Num: P02-17498R; LIFECYCLE_PHASE: Active; MFR_LIFECYCLE: Active; Manufacturer: Panasonic; Manufacturer Part Num: ERJ-2RKF1153X; Num Pins: 2; PART_SUBCLASS: RESISTORS; POWER: 1/16W; RoHS Compliant: RoHS Compliant; TOLERANCE: +/-1%
R99 R305 = RESISTOR_0402: RES 21.0K OHM 1/16W 1% 0402 SMD; AGILE_LINK: http://sj-agile9app/Agile/PLMServlet?action=OpenEmailObject&classid=10000&objid=197674503; IPN: K21582-001; Item Num: P02-14046R; LIFECYCLE_PHASE: Active; MFR_LIFECYCLE: Active; Manufacturer: Panasonic; Manufacturer Part Num: ERJ-2RKF2102X; Num Pins: 2; PART_SUBCLASS: RESISTORS; POWER: 1/16W; RoHS Compliant: RoHS Compliant; TOLERANCE: +/-1%
R101 = RES_16.5K_OHM_1_10W_1%_0402: IPN: A80006-001; Manufacturer Part Num: ERJ-2RKF1652X
R102 R1131 = RES_13.7K_OHM,_1_16W,_1%,_0402: RES 13.7KOHM, 1/16W, 1%, 0402, SMD; IPN: A93548-377; Manufacturer Part Num: CRCW040213K7FKED
R90 R294 R300 = RES_100K_OHM_1.0%_1_16W_0402: IPN: A93548-596
R103 R253 R310 R311 = RES_10_OHM_1.0%_1_16W_0402: IPN: A80345-001
U24 = LTC3613EWKH_7: REG - 24V, 15A MONOLITHIC STEP DOWN REGULATOR WITH DIFFERENTIAL OUTPUT SENSING, QFN-56; IPN: H38116-001; Item Num: P05-18723R; Manufacturer: Linear Technology; Manufacturer Part Num: LTC3613EWKH#PBF
C95 = Cap_3300PF_10%_50V_0402: CAP, CERAMIC, 3300PF, 10%, 50V, X7R, 0402; IPN: K13754-001; Manufacturer: Murata; Manufacturer Part Num: GRM155F51H332ZA01x
C98 = CAP: CAP,CER,68PF,0402,5%,50VDC,N; AGILE_LINK: http://sj-agile9app/Agile/PLMServlet?action=OpenEmailObject&classid=10000&objid=256956561; IPN: A36095-041; Item Num: P03-11353R; LIFECYCLE_PHASE: Active; MFR_LIFECYCLE: Active; Manufacturer: Panasonic; Manufacturer Part Num: ECJ-0EC1H680J; Num Pins: 2; PART_SUBCLASS: CAPACITORS; RATED_VOLTAGE: 50V; RoHS Compliant: RoHS Compliant; TOLERANCE: 5%
C99 = Cap_39PF_5%_50V_0402: IPN: A36095-021
C107 = Cap_2.2uF_+_-20%_6.3V_0402: IPN: H68861-001
C108 = Cap_1.0UF_10%_6.3V_0603: IPN: H86538-001; Manufacturer: Panasonic; Manufacturer Part Num: ECJ-1VB0J105K
C111 C112 C506 C507 = CAP_22uF_+_-10%_6.3V_0805: IPN: K13617-001
C113 = Cap_0.1UF_25VDC_0402: CAP - CERAMIC, 0.1UF 0402 25VDC Y5V; IPN: K13560-001
C488 = Cap_0.1UF_50V_0603: IPN: M31986-001; Manufacturer: Panasonic; Manufacturer Part Num: C0603C104K5REC
L8 = IND_1.2uH_Ir=6.5A_CUBE_SMD: IPN: K14427-001
L5 L13 = BEAD_FERRITE_SM: IND - FERRITE BEAD, 3A, 30 OHM@100MHz, 40mOhm Max, 0603; IPN: K14405-001; Item Num: P04-16965R; Lead Free Status: No; Manufacturer: Wurth; Manufacturer Part Num: 742792609; Num Pins: 2; Part Class: Inductors; Price: 0; RoHS Compliant: Yes
R89 R91 R93 R94 R96 R299 = RES_10.0K_OHM_1.0%_1_16W_0402: IPN: A93548-034
R100 = RESISTOR: RES - 316K OHM, 1%,1/10W, 0402 SMD; IPN: K21611-001; Item Num: P02-16670R; Manufacturer: Panasonic; Manufacturer Part Num: ERJ-2RKF3163x
R53 R79 R307 = RES_0.003_OHM_1%_1_2W_2010: IPN: C14411-035
U25 = Reg_switching,_LTC3605EUF: IPN: K15491-001
C42 C77 = CAP: CAP - CERAMIC, 10UF, 10%, 10VDC, 0805, X5R; Dielectric: X7R; IPN: K13557-001; Item Num: P03-15116R; MFR_LIFECYCLE: Active; Manufacturer: Murata; Manufacturer Part Num: GRM21BR61A106KE19L; Num Pins: 2; PART_SUBCLASS: CAPACITORS; Part Class: Capacitors; Price: 0; RoHS Compliant: Yes; Working Voltage: 10V
C43 C74 = CAP: CAP, CERAMIC, 1UF, 0402, 10%, 10VDC,  X5R; IPN: A36096-099; Item Num: P03-15010R; Lead Free Status: No; Manufacturer: Panasonic; Manufacturer Part Num: ECJ-0EB1A105M; Num Pins: 2; Part Class: Capacitors; Price: 0; RoHS Compliant: Yes
C46 = CAP: CAP - CERM, 10PF, 5%, 50V, C0G/NP0, 0402; AGILE_LINK: http://sj-agile9app/Agile/PLMServlet?action=OpenEmailObject&classid=10000&objid=242850580; IPN: K13759-001; Item Num: P03-16652R; Manufacturer: Murata; Manufacturer Part Num: GRM1555C1H100JZ01D; Num Pins: 2; PART_SUBCLASS: CAPACITORS; RATED_VOLTAGE: 50V; TOLERANCE: 5%; Working Voltage: 50V
C49 C85 = CAP: CAP, CERAMIC, 2.2UF, 10%, 10VDC, X5R, 0603; AGILE_LINK: http://sj-agile9app/Agile/PLMServlet?action=OpenEmailObject&classid=10000&objid=256999866; IPN: M97320-001; Item Num: P03-15213R; LIFECYCLE_PHASE: Active; Lead Free Status: Lead Free; MFR_LIFECYCLE: Active; Manufacturer: Murata; Manufacturer Part Num: GRM188R61A225KE34x; Num Pins: 2; PART_SUBCLASS: CAPACITORS; RATED_VOLTAGE: 10V; RoHS Compliant: RoHS Compliant; Supplier Part Num: 490-1545-1-ND; TOLERANCE: +/-10%
C68 C81 C359 C374 = CAP_47UF_+_-20%_6.3V_1206: IPN: 108427-365
C100 = Cap_1000PF_10%_50V_0402: CAP - CERAMIC, 1000PF 50V 10% X7R 0402; IPN: A36096-004
C387 = CAP: CAP - CERAMIC 22UF 10V X5R 10% 1210; AGILE_LINK: http://sj-agile9app/Agile/PLMServlet?action=OpenEmailObject&classid=10000&objid=216565517; IPN: K13608-001; Item Num: P03-15081R; LIFECYCLE_PHASE: Active; Lead Free Status: Lead Free; MFR_LIFECYCLE: Active; Manufacturer: Murata; Manufacturer Part Num: GRM32ER61A226KE20L; Num Pins: 2; PART_SUBCLASS: CAPACITORS; RATED_VOLTAGE: 10V; RoHS Compliant: RoHS Compliant; TOLERANCE: +/-10%
C423 = Cap_4.7uF_+_-10%_16V_0805: IPN: M97318-001
C424 = Cap_0.22UF_10%_10V_0402: CAP - CERAMIC, 0.22UF, 10V, X5R, 10%, 0402; IPN: A36096-078
C441 = CAP: CAP - CER, 470PF, 10%, 50V, X7R, 0402; IPN: A36096-003; Item Num: P03-15176R; LIFECYCLE_PHASE: Active; MFR_LIFECYCLE: Active; Manufacturer: Murata; Manufacturer Part Num: GRM155R71H471KA01D; Num Pins: 2; PART_SUBCLASS: CAPACITORS; RATED_VOLTAGE: 50V; RoHS Compliant: RoHS Compliant; TOLERANCE: 10%
C442 = CAP: CAP - CER, 15PF, 50V, +/-5%, C0G, 0402 SMD; IPN: A36095-047; Item Num: P03-16322R; LIFECYCLE_PHASE: Active; Lead Free Status: Lead Free; MFR_LIFECYCLE: Active; Manufacturer: Panasonic; Manufacturer Part Num: ECJ-0EC1H150J; Num Pins: 2; PACKAGING: Tape & Reel (TR); PART_SUBCLASS: CAPACITORS; RATED_VOLTAGE: 50V; RoHS Compliant: RoHS Compliant; Tolerance: +/-5%
R64 = RESISTOR: RES - 187 OHM 1/16W 1% 0402 SMD; AGILE_LINK: http://sj-agile9app/Agile/PLMServlet?action=OpenEmailObject&classid=10000&objid=257345545; IPN: K15740-001; Item Num: P02-14348R; LIFECYCLE_PHASE: Active; Lead Free Status: Lead Free; MFR_LIFECYCLE: Active; Manufacturer: Panasonic; Manufacturer Part Num: ERJ-2RKF1870X; Num Pins: 2; PART_SUBCLASS: RESISTORS; POWER: 1/16W; RoHS Compliant: RoHS Compliant; TOLERANCE: +/-1%
R69 = RESISTOR: RES - 1.50K OHMS, 1%, 1/16W, 0402; AGILE_LINK: http://sj-agile9app/Agile/PLMServlet?action=OpenEmailObject&classid=10000&objid=258802890; IPN: A80347-001; Item Num: P02-15207R; LIFECYCLE_PHASE: Active; Lead Free Status: Lead Free; MFR_LIFECYCLE: Active; Manufacturer: Panasonic; Manufacturer Part Num: ERJ-2RKF1501X; Num Pins: 2; PART_SUBCLASS: RESISTORS; POWER: 1/16W; RESISTANCE: 1.5K; RoHS Compliant: RoHS Compliant; TOLERANCE: +/-1%
R219 = RESISTOR: RES, 499K OHM,1%, 1/16W, 0402, SM; IPN: G42210-001; Item Num: P02-14134R; LIFECYCLE_PHASE: Active; Lead Free Status: No; MFR_LIFECYCLE: Active; Manufacturer: Panasonic; Manufacturer Part Num: ERJ-2RKF4993X; Num Pins: 2; PART_SUBCLASS: RESISTORS; POWER: 1/16W; RoHS Compliant: Yes; TOLERANCE: +/-1%
R295 = RES_9.53K_OHMS_1%_1_16W_0402: IPN: H95112-001
R296 = RES_30.1K_OHM_1%_1_16W_0402_SMD: IPN: E78921-001
R297 = RES_75K_OHM_1%_1_16W_0402_SMD: IPN: A93548-325
U10 = LTC3085EDCB: REG - LDO, 500MA, 1.2V-36V INPUT, 0V-36V OUTPUT, 275MV DROPOUT, (2X3X0.75)MM 6-DFN; IPN: K15496-001; Item Num: P05-18643R; Manufacturer: Linear Technology; Manufacturer Part Num: LT3085EDCB#PBF
U18 = LT3022EDHC: REG - VLDO, 1A, 0.9V-10V INPUT, ADJ OUTPUT, 145MV DROPOUT, (5X3X0.75)MM 16-DFN; IPN: J12555-001; Item Num: P05-18644R; Manufacturer: Linear Technology; Manufacturer Part Num: LT3022EDHC#PBF; PART_SUBCLASS: REGULATORS; RoHS Compliant: RoHS Compliant
U21 = Reg_Switching,_LTC3608: IPN: K15493-001
BT1 = Battery_0: SOCKET - BATTERY; IPN: K12205-001; Item Num: P23-38491R; Manufacturer: Keystone Electronics; Manufacturer Part Num: 1060TR; RoHS Compliant: Yes
C188 = CAP: CAP - CER, 47000PF, 25V, X7R, 0402; IPN: K13558-001; Item Num: P03-15073R; Lead Free Status: Yes; Manufacturer: Murata; Manufacturer Part Num: GRM155R71E473KA88D; Num Pins: 2; Part Class: Capacitors; Price: 0; RoHS Compliant: Yes; Supplier Part Num: GRM155R71E473KA88D
R184 R216 = RESISTOR: RES,100 OHMS,1.0%,1/16W,0402; IPN: A36092-043; Item Num: P02-11381R; Lead Free Status: No; Manufacturer: Panasonic; Manufacturer Part Num: ERJ-2RKF1000X; Num Pins: 2; Part Class: Resistors; Price: 0; RoHS Compliant: Yes; Tolerance: 1%

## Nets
1.1V_REG_VCC: C87.1 C88.1 R70.1 R78.2 R102.1 U24.18(VOUT) V36.1(RSNS) ; also on sheet 29
1.8V: C85.1 C387.1 R69.2 R79.1 U18.3(VOUT) U18.4(VOUT) ; also on sheet 8 14 15 19 20 21 29
1.8V_ADJ: R64.2 R69.1 U18.5(ADJ)
2.5V: C68.1 C74.1 C77.1 C81.1 C359.1 C374.1 L6.2 R53.1 R249.2 R296.1 U18.9(~{SHDN}) U18.12(VIN) U18.13(VIN) U18.14(VIN) U21.13(VON) ; also on sheet 3 8 10 11 15 17 19 20 29
2.5V_VCCBAT_SKT: R248.2 R249.1 R253.1
3.3V: R86.1 R89.1 R90.1 R96.1 R264.1 R300.1 ; also on sheet 8 14 16 18 19 20 21 27 28
3.3V_ITEMP1: R226.1 U40.37(ITEMP1)
3.3V_MUX: C48.1 C248.1 D31.1(VIN) D31.12(SOURCE) L4.2 R55.1 R191.2 U17.1(S1) U17.2(S2) U17.3(S3) U40.10(DIFFP) V3.2(SNS)
3.3V_MUXVCC: C358.2 D31.2(VCC) D31.3(UV)
3.3V_MUXVCCP: C383.2 D33.2(VCC) D33.3(UV)
3.3V_OUT: D31.8(OUT) D33.8(OUT) R55.2 R264.2 R271.2 U17.5(D) U19.5(D)
3.3V_PCIE: D33.1(VIN) D33.12(SOURCE) R271.1 U19.1(S1) U19.2(S2) U19.3(S3) ; also on sheet 3
3.3V_SHDNn: R17.2 SW2.2 U40.38(RUN1)
5.0V: C49.1 R178.2 R213.2 U10.1(OUT) U10.2(OUT) ; also on sheet 20 27 29
12V: C42.1 C43.1 C76.1 C114.1 C115.1 C116.1 C117.1 C375.1 C420.1 C489.1 C508.1 R103.2 R252.2 R297.1 U10.4(Vcontrol) U10.5(IN) U10.6(IN) U21.1(PVIN) U21.2(PVIN) U21.3(PVIN) U21.4(PVIN) U21.5(PVIN) U21.6(PVIN) U21.7(PVIN) U21.30(SVIN) U21.48(PVIN) U21.49(PVIN) U21.50(PVIN) U21.51(PVIN) U21.52(PVIN) U21.53(PVIN_EPAD) U24.1(PVIN1) U24.2(PVIN7) U24.3(PVIN8) U24.4(PVIN9) U24.5(PVIN10) U24.6(PVIN11) U24.7(PVIN12) U24.8(PVIN13) U24.9(PVIN14) U24.32(SVIN1) U24.53(PVIN6) U24.54(PVIN5) U24.55(PVIN4) U24.56(PVIN3) U24.57(PVIN2) U25.17(PVIN) U25.18(PVIN) ; also on sheet 18 27 28 29
12V_ITEMP2: R225.1 U40.36(ITEMP2)
12V_MUX: C32.1 C187.1 C216.1 L3.2 R214.2 U14.1(S1) U14.2(S2) U14.3(S3) U44.2(IN) V1.2(SNS)
12V_OUT: R252.1 U14.5(D) U16.5(D) U44.1(OUT) U44.6(VDD) U46.1(OUT) U46.6(VDD)
12V_PCIE: U16.1(S1) U16.2(S2) U16.3(S3) U46.2(IN) ; also on sheet 3
12V_SHDNn: R14.2 SW2.5 U40.13(RUN2)
GND: BT1.1(NEG) C32.2 C41.2 C42.2 C43.2 C46.1 C48.2 C49.2 C65.2 C68.2 C69.2(CATHODE) C74.2 C76.2 C77.2 C81.2 C85.2 C87.2 C88.2 C94.1 C95.1 C98.1 C100.1 C101.1 C106.1 C107.2 C108.1 C111.2 C112.2 C113.1 C114.2 C115.2 C116.2 C117.2 C186.2 C187.2 C188.2 C208.2 C212.2 C215.2 C216.2 C225.2 C232.2 C244.2 C246.2 C248.2 C264.2 C334.2 C358.1 C359.2 C374.2 C375.2 C383.1 C387.2 C416.2 C419.2 C420.2 C423.2 C438.2 C442.1 C489.2 C506.2 C507.2 C508.2 D21.2(CATHODE) D31.4(OV) D31.7(REV) D31.9(GND) D31.13(EP) D33.4(OV) D33.7(REV) D33.9(GND) D33.13(EP) D39.1(CATHODE1) J8.2 J8.3 Q2.1 Q2.2 Q2.3 Q3.1 Q3.2 Q3.3 R14.1 R17.1 R64.1 R87.2 R88.1 R94.2 R100.2 R101.1 R200.2 R201.2 R203.1 R215.1 R216.2 R219.2 R220.2 R224.1 R225.2 R226.2 R228.1 R283.1 R295.2 R299.2 R305.2 U10.7(EP_GND) U13.A4(GND) U13.A9(GND) U13.A19(GND) U13.A29(GND) U13.AA3(GND) U13.AA4(GND) U13.AA5(GND) U13.AA6(GND) U13.AA8(GND) U13.AA10(GND) U13.AA12(GND) U13.AA14(GND) U13.AA19(GND) U13.AA29(GND) U13.AA34(GND) U13.AB1(GND) U13.AB2(GND) U13.AB5(GND) U13.AB6(GND) U13.AB7(GND) U13.AB9(GND) U13.AB11(GND) U13.AB12(GND) U13.AB22(GND) U13.AB32(GND) U13.AC3(GND) U13.AC4(GND) U13.AC5(GND) U13.AC6(GND) U13.AC8(GND) U13.AC10(GND) U13.AC15(GND) U13.AC25(GND) U13.AD1(GND) U13.AD2(GND) U13.AD5(GND) U13.AD6(GND) U13.AD7(GND) U13.AD9(GND) U13.AD10(GND) U13.AD18(GND) U13.AD28(GND) U13.AE3(GND) U13.AE4(GND) U13.AE5(GND) U13.AE6(GND) U13.AE7(GND) U13.AE8(GND) U13.AE9(GND) U13.AE11(GND) U13.AE21(GND) U13.AE27(VREFB5AN0) U13.AE31(GND) U13.AF1(GND) U13.AF2(GND) U13.AF5(GND) U13.AF6(GND) U13.AF7(GND) U13.AF14(GND) U13.AF24(GND) U13.AF34(GND) U13.AG3(GND) U13.AG4(GND) U13.AG5(GND) U13.AG6(GND) U13.AG7(GND) U13.AG17(GND) U13.AG27(GND) U13.AH1(GND) U13.AH2(GND) U13.AH5(GND) U13.AH10(GND) U13.AH11(VREFB3AN0) U13.AH20(GND) U13.AH30(GND) U13.AJ3(GND) U13.AJ4(GND) U13.AJ5(GND) U13.AJ13(GND) U13.AJ23(GND) U13.AJ33(GND) U13.AK1(GND) U13.AK2(GND) U13.AK3(GND) U13.AK6(GND) U13.AK16(GND) U13.AK26(GND) U13.AL5(GND) U13.AL9(GND) U13.AL19(GND) U13.AL29(GND) U13.AL34(GND) U13.AM3(GND) U13.AM12(GND) U13.AM22(GND) U13.AM32(GND) U13.AN6(GND) U13.AN15(GND) U13.AN25(GND) U13.AP2(GND) U13.AP4(GND) U13.AP8(GND) U13.AP13(GND) U13.AP18(GND) U13.AP23(GND) U13.AP28(GND) U13.AP33(GND) U13.B2(GND) U13.B22(GND) U13.B32(GND) U13.B34(GND) U13.C3(GND) U13.C4(GND) U13.C5(GND) U13.C15(GND) U13.C25(GND) U13.D1(GND) U13.D2(GND) U13.D5(GND) U13.D8(GND) U13.D18(GND) U13.D28(GND) U13.D33(GND) U13.E2(GND) U13.E3(GND) U13.E4(GND) U13.E5(GND) U13.E11(GND) U13.E21(GND) U13.E31(GND) U13.F1(GND) U13.F2(GND) U13.F5(GND) U13.F14(GND) U13.F24(GND) U13.F34(GND) U13.G3(GND) U13.G4(GND) U13.G5(GND) U13.G7(GND) U13.G16(VREFB8AN0) U13.G17(GND) U13.G27(GND) U13.H1(GND) U13.H2(GND) U13.H5(GND) U13.H8(GND) U13.H10(GND) U13.H20(GND) U13.H30(GND) U13.J3(GND) U13.J4(GND) U13.J5(GND) U13.J13(GND) U13.J23(GND) U13.J26(GND) U13.J33(GND) U13.K1(GND) U13.K2(GND) U13.K5(GND) U13.K6(GND) U13.K7(GND) U13.K8(GND) U13.K16(GND) U13.K26(GND) U13.L3(GND) U13.L4(GND) U13.L5(GND) U13.L6(GND) U13.L7(GND) U13.L8(GND) U13.L9(GND) U13.L14(GND) U13.L19(GND) U13.L24(GND) U13.L29(GND) U13.L34(GND) U13.M1(GND) U13.M2(GND) U13.M5(GND) U13.M6(GND) U13.M7(GND) U13.M9(GND) U13.M10(GND) U13.M12(GND) U13.M17(GND) U13.M22(GND) U13.M32(GND) U13.N3(GND) U13.N4(GND) U13.N5(GND) U13.N6(GND) U13.N8(GND) U13.N10(GND) U13.N11(GND) U13.N16(GND) U13.N18(GND) U13.N20(GND) U13.N25(GND) U13.P1(GND) U13.P2(GND) U13.P5(GND) U13.P6(GND) U13.P7(GND) U13.P9(GND) U13.P11(GND) U13.P13(GND) U13.P15(GND) U13.P17(GND) U13.P19(GND) U13.P21(GND) U13.P28(GND) U13.R3(GND) U13.R4(GND) U13.R5(GND) U13.R6(GND) U13.R8(GND) U13.R10(GND) U13.R12(GND) U13.R14(GND) U13.R16(GND) U13.R18(GND) U13.R20(GND) U13.R22(GND) U13.R31(GND) U13.T1(GND) U13.T2(GND) U13.T5(GND) U13.T6(GND) U13.T7(GND) U13.T9(GND) U13.T11(GND) U13.T13(GND) U13.T15(GND) U13.T17(GND) U13.T19(GND) U13.T21(GND) U13.T24(GND) U13.T34(GND) U13.U3(GND) U13.U4(GND) U13.U5(GND) U13.U6(GND) U13.U8(GND) U13.U10(GND) U13.U12(GND) U13.U14(GND) U13.U16(GND) U13.U18(GND) U13.U20(GND) U13.U22(GND) U13.U27(GND) U13.V1(GND) U13.V2(GND) U13.V5(GND) U13.V6(GND) U13.V7(GND) U13.V9(GND) U13.V11(GND) U13.V13(GND) U13.V15(GND) U13.V17(GND) U13.V19(GND) U13.V21(GND) U13.V30(GND) U13.W3(GND) U13.W4(GND) U13.W5(GND) U13.W6(GND) U13.W8(GND) U13.W10(GND) U13.W12(GND) U13.W14(GND) U13.W16(GND) U13.W18(GND) U13.W20(GND) U13.W22(GND) U13.W23(GND) U13.W33(GND) U13.Y1(GND) U13.Y2(GND) U13.Y5(GND) U13.Y6(GND) U13.Y7(GND) U13.Y9(GND) U13.Y10(GND) U13.Y11(GND) U13.Y13(GND) U13.Y15(GND) U13.Y17(GND) U13.Y19(GND) U13.Y21(GND) U18.6(AGND) U18.7(AGND) U18.10(PGND) U18.11(PGND) U18.17(EP_GND) U21.10(SGND) U21.14(SGND) U21.15(SGND) U21.20(SGND) U21.26(SGND) U21.27(SGND) U21.34(PGND) U21.35(PGND) U21.36(PGND) U21.37(PGND) U21.38(PGND) U21.39(PGND) U21.40(PGND) U21.54(SGND_EPAD) U24.12(SGND) U24.16(SGND3) U24.17(SGND4) U24.19(SGND5) U24.20(VOSNS-) U24.28(SGND6) U24.29(SGND7) U24.36(PGND1) U24.37(PGND9) U24.38(PGND8) U24.39(PGND7) U24.40(PGND6) U24.41(PGND5) U24.42(PGND4) U24.43(PGND3) U24.44(PGND2) U24.59(SGND2) U25.10(PGND) U25.22(SGND) U25.24(CLKIN) U25.25(PGND) U40.4(SGND1) U40.11(DIFFN) U40.22(PGND2) U40.28(PGND1) U40.41(SGND2) U44.4(GND) U44.7(EP_GND) U46.4(GND) U46.7(EP_GND) ; also on sheet 3 4 6 7 8 9 10 11 12 13 14 15 16 17 18 19 20 21 27 28 29 30
VCCBAT: C334.1 R253.2 U13.H9(VCCBAT)
C5_2.5V: L5.1 U13.AC11(VCCA_FPLL) U13.AD26(VCCA_FPLL) U13.AE12(VCC_AUX) U13.AE18(VCC_AUX) U13.AE24(VCC_AUX) U13.J10(VCC_AUX) U13.K18(VCC_AUX) U13.K24(VCC_AUX) U13.M11(VCCA_FPLL) U13.M26(VCCA_FPLL) ; also on sheet 7 30
C5_2.5V_BOOST: C424.1 D41.1 U21.11(BOOST)
C5_2.5V_INTVCC: C423.1 D41.2 R298.1 U21.19(FCB) U21.31(INTVCC) U21.32(INTVCC)
C5_2.5V_ION: R297.2 U21.22(ION)
C5_2.5V_ITH: C441.2 C442.2 R298.2 U21.18(ITH)
C5_2.5V_ITH_CR: C441.1 R305.1
C5_2.5V_RUN: C100.2 R95.2 R96.2 U21.12(RUN/SS)
C5_2.5V_SW: C424.2 L6.1 U21.8(SW) U21.33(SW) U21.41(SW) U21.42(SW) U21.43(SW) U21.44(SW) U21.45(SW) U21.46(SW) U21.47(SW) U21.55(SW_EPAD)
C5_2.5V_VFB: R295.1 R296.2 U21.23(VFB)
C5_2.5V_VRNG: R299.1 U21.17(VRNG)
C5_GXB_1.2V: C99.1 C111.1 C112.1 C506.1 C507.1 L8.2 R93.1 R307.1 U25.9(VON) ; also on sheet 29
C5_GXB_BOOST: C488.1 D43.1 U25.20(BOOST)
C5_GXB_FB: C99.2 R93.2 R94.1 U25.4(FB)
C5_GXB_INTVCC: C107.1 C108.2 D43.2 R92.1 U25.2(PHMODE) U25.3(MODE) U25.21(INTVCC)
C5_GXB_ITH: C98.2 R91.2 R92.2 U25.6(ITH)
C5_GXB_RT: R100.1 U25.1(RT)
C5_GXB_RUN: R84.2 R89.2 U25.7(RUN)
C5_GXB_SS: C95.2 U25.5(TRACK/SS)
C5_GXB_SVIN: C113.2 R103.1 U25.19(SVIN)
C5_GXB_SW: C488.2 L8.1 U25.11(SW) U25.12(SW) U25.13(SW) U25.14(SW) U25.15(SW) U25.16(SW)
C5_VCC: C69.1(ANODE) R70.2 R1131.1 U13.AA13(VCC) U13.N15(VCC) U13.N17(VCC) U13.N19(VCC) U13.N21(VCC) U13.P12(VCC) U13.P16(VCC) U13.P18(VCC) U13.P20(VCC) U13.P22(VCC) U13.R13(VCC) U13.R15(VCC) U13.R17(VCC) U13.R19(VCC) U13.R21(VCC) U13.T12(VCC) U13.T14(VCC) U13.T16(VCC) U13.T18(VCC) U13.T20(VCC) U13.T22(VCC) U13.U13(VCC) U13.U15(VCC) U13.U17(VCC) U13.U19(VCC) U13.U21(VCC) U13.V12(VCC) U13.V14(VCC) U13.V16(VCC) U13.V18(VCC) U13.V20(VCC) U13.V22(VCC) U13.W13(VCC) U13.W15(VCC) U13.W17(VCC) U13.W19(VCC) U13.W21(VCC) U13.Y12(VCC) U13.Y14(VCC) U13.Y16(VCC) U13.Y18(VCC) ; also on sheet 29 30
C5_VCC_BOOST: C110.1 D42.1 U24.11(BOOST)
C5_VCC_INTVCC: C416.1 D42.2 R279.2 R282.1 R294.2 U24.33(INTVCC2) U24.34(INTVCC1)
C5_VCC_MODE: R282.2 R283.2 U24.31(MODE/PLLIN)
C5_VCC_REF: R101.2 R102.2 R1131.2 U24.21(VOSNS+)
C5_VCC_SNS_N: R310.1 V36.2(SNS)
C5_VCC_SNS_P: R311.1 V35.2(SNS)
C5_VCC_SW: C110.2 L7.1 U24.10(SW1) U24.35(SW2) U24.45(SW9) U24.46(SW8) U24.47(SW7) U24.48(SW6) U24.49(SW5) U24.50(SW4) U24.51(SW3) U24.58(SW2)
C5_VCC_TRACK: C106.2 U24.22(TRACK/SS)
C5_VCC_VOUT: L7.2 R78.1 V35.1(RSNS)
C5_VCCE_GXBL: L13.2 R307.2 ; also on sheet 7 29 30
C5_VCCIO_1.5V: U13.AB17(VCCIO3B) U13.AC20(VCCIO4A) U13.AC30(VCCIO5B) U13.AD23(VCCIO4A) U13.AD33(VCCIO5B) U13.AE16(VCCIO3B) U13.AF19(VCCIO4A) U13.AG22(VCCIO4A) U13.AG32(VCCIO5B) U13.AH15(VCCIO3B) U13.AH25(VCCIO4A) U13.AJ18(VCCIO4A) U13.AJ28(VCCIO4A) U13.AK21(VCCIO4A) U13.AL14(VCCIO3B) U13.AL24(VCCIO4A) U13.AM17(VCCIO3B) U13.AM27(VCCIO4A) U13.AN10(VCCIO3B) U13.AN20(VCCIO4A) U13.AN30(VCCIO4A) U13.G32(VCCIO6A) U13.J28(VCCIO6A) U13.K31(VCCIO6A) U13.M27(VCCIO6A) U13.N30(VCCIO6A) U13.P23(VCCIO6A) U13.P33(VCCIO6A) U13.R26(VCCIO6A) U13.T29(VCCIO6A) U13.U32(VCCIO6A) U13.V25(VCCIO5B) U13.W28(VCCIO5B) U13.Y31(VCCIO5B) ; also on sheet 27 29 30
C5_VCCIO_1.8V: R79.2 U13.AA24(VCCIO5A) U13.AB27(VCCIO5A) U13.AE26(VCCIO5A) U13.AF29(VCCIO5A) U13.AK31(VCCIO5A) U13.Y26(VCCIO5A) ; also on sheet 29 30
C5_VCCIO_2.5V: L5.2 R53.2 U13.A14(VCCIO8A) U13.AA26(VCCPD5A) U13.AB26(VCCPD5A) U13.AD13(VCCIO3A) U13.AD27(VCCPGM) U13.AE13(VCCPD3A) U13.AE15(VCCPD3A) U13.AE17(VCCPD3B4A) U13.AE22(VCCPD3B4A) U13.AF9(VCCIO3A) U13.AF12(VCCPGM) U13.AF15(VCCPD3B4A) U13.AF16(VCCPD3B4A) U13.AF20(VCCPD3B4A) U13.AF21(VCCPD3B4A) U13.AG12(VCCIO3A) U13.AJ8(VCCIO3A) U13.AK11(VCCIO3A) U13.AM7(VCCIO3A) U13.B7(VCCIO8A) U13.B12(VCCIO8A) U13.B17(VCCIO8A) U13.C10(VCCIO8A) U13.D13(VCCIO8A) U13.E6(VCCIO8A) U13.E16(VCCIO8A) U13.F9(VCCIO8A) U13.G12(VCCIO8A) U13.H11(VCCPGM) U13.H15(VCCIO8A) U13.J14(VCCPD7A8A) U13.J16(VCCPD7A8A) U13.J19(VCCPD7A8A) U13.J21(VCCPD7A8A) U13.J22(VCCPD7A8A) U13.K11(VCCIO8A) U13.K15(VCCPD7A8A) U13.K17(VCCPD7A8A) U13.K20(VCCPD7A8A) U13.N26(VCCPD6A) U13.P26(VCCPD6A) U13.T26(VCCPD6A) U13.U26(VCCPD6A) U13.V26(VCCPD5B) U13.W25(VCCPD5B) ; also on sheet 10 29 30
C5_VCCIO_VAR: C188.1 R184.1 U13.A24(VCCIO7A) U13.B27(VCCIO7A) U13.C20(VCCIO7A) U13.C30(VCCIO7A) U13.D23(VCCIO7A) U13.E26(VCCIO7A) U13.F19(VCCIO7A) U13.F29(VCCIO7A) U13.G22(VCCIO7A) U13.H25(VCCIO7A) U13.J18(VCCIO7A) U13.K21(VCCIO7A) ; also on sheet 28 29 30
C5_VCCL_GXBL: L13.1 ; also on sheet 7 30
DC_IN: C41.1 C65.1 C186.1 C212.1 C232.1 C244.1 Q1.5 Q4.5 R21.2 R31.2 U9.5(D) U40.26(VIN) U41.1(OUT) U41.6(VDD)
DC_INPUT: D39.2(CATHODE2) J8.1 U9.1(S1) U9.2(S2) U9.3(S3) U41.2(IN)
DIFFOUT: R221.1 U40.12(DIFFOUT)
EXTVCC: U21.29(EXTVCC)
INTVCC_1: C225.1 D38.2 D40.2 R192.1 R199.1 U40.25(INTVCC)
LTC3855_S1N: C245.2 R227.2 U40.40(SENSE1-) V3.1(RSNS)
LTC3855_S1P: C245.1 R227.1 R236.1 U40.39(SENSE1+)
LTC3855_S2N: C207.2 R194.2 U40.9(SENSE2-) V1.1(RSNS)
LTC3855_S2P: C207.1 R193.1 R194.1 U40.8(SENSE2+)
PG_12V: R191.1 U40.17(PGOOD2)
PGD_C5_VCC: R294.1 R303.1 U24.13(PGOOD)
PGOOD_C5_2.5V: R300.2 U21.16(PGOOD)
PGOOD_C5_GXB_1.2V: R83.1 R90.2 U25.8(PGOOD)
PGOOD_C5_VCC: R83.2 R84.1 R95.1 R303.2 ; also on sheet 27 28
RUN_C5_VCC: R86.2 U24.26(RUN)
SW1: C233.2 L4.1 Q3.5 Q4.1 Q4.2 Q4.3 U40.31(SW1) V4.2(SNS)
SW2: C213.2 L3.1 Q1.1 Q1.2 Q1.3 Q2.5 U40.19(SW2) V2.2(SNS)
VFB2: R214.1 R215.2 U40.5(VFB2)
VREF_DDR3A: U13.AG20(VREFB4AN0) U13.AH18(VREFB3BN0) ; also on sheet 12 27 30
VREF_DDR3B: U13.P29(VREFB6AN0) U13.V29(VREFB5BN0) ; also on sheet 13 27 30
VREF_HSMB: R184.2 R216.1 U13.G19(VREFB7AN0)
N122272241: D21.1(ANODE) R178.1
N122272248: R220.1 R221.2 U40.3(VFB1)
N122272251: Q2.4(GATE) U40.23(BG2)
N122272269: C213.1 D38.1 U40.21(BOOST2)
N122272297: C214.1 C215.1 U40.6(ITH2)
N122272299: C233.1 D40.1 U40.29(BOOST1)
N122272311: C264.1 U40.1(TK/SS1)
N122272319: C208.1 U40.7(TK/SS2)
N122272321: C214.2 R203.2
N122272339: R224.2 U40.35(FREQ)
N122272371: C246.1 C247.1 U40.2(ITH1)
N122272384: C247.2 R228.2
N122272390: Q4.4(GATE) U40.30(TG1)
N122272433: D31.11(GATE) U17.4(G)
N122272456: D33.11(GATE) U19.4(G)
N122272495: U14.4(G) U44.3(GATE)
N122272528: U16.4(G) U46.3(GATE)
N122272540: R31.1 SW2.4
N122272542: R21.1 SW2.1
N122272556: Q1.4(GATE) U40.20(TG2)
N122272581: R236.2 V4.1(RSNS)
N122272597: R193.2 V2.1(RSNS)
N122272631: U9.4(G) U41.3(GATE)
N122272648: D39.3(ANODE) U41.4(GND) U41.7(EP_GND)
N123344791: R199.2 R200.1 U40.15(ILIM2)
N123344797: R192.2 R201.1 U40.14(ILIM1)
N126528258: C479.2 R311.2 U24.14(SNS+)
N126528264: C419.1 U24.30(EXTVCC)
N126528287: C479.1 R310.2 U24.15(SNS-)
N126528328: C101.2 R99.1 U24.23(ITH)
N126528339: R87.1 U24.25(RT)
N126528349: R88.2 R279.1 U24.24(VRNG)
N126528357: C438.1 R99.2
N126536082: C94.2 R91.1
N126906414: Q3.4(GATE) U40.27(BG1)
N126964562: BT1.2(POS2) BT1.3(POS3) R248.1
N127147799: R213.1 U40.24(EXTVCC)
N127496195: C46.2 R219.1 U10.3(SET)

Not connected (* = marked no-connect by the designer): D31 5(~{STATUS}) 6(~{FAULT}) 10(CPO); D33 5(~{STATUS}) 6(~{FAULT}) 10(CPO); SW2 3* 6*; U13 A30(NC42)* A31(NC43)* A32(NC44)* A33(NC45)* AF8(NC15)* AF17(DNU3)* AG8(NC14)* AG9(DNU2)* AH6(NC12)* AH7(NC13)* AK4(NC11)* AL1(NC7)* AL2(NC8)* AL3(NC9)* AL4(NC10)* AM1(NC5)* AM2(NC6)* AN1(NC2)* AN2(NC3)* AN3(NC4)* AP3(NC1)* B33(NC41)* C2(NC37)* C19(NC38)* C33(NC39)* C34(NC40)* D3(DNU1)* D4(DNU0)* D6(NC33)* D31(NC34)* D32(NC35)* D34(NC36)* E32(NC30)* E33(NC31)* E34(NC32)* F31(NC27)* F32(NC28)* F33(NC29)* G6(NC26)* H6(NC25)* J6(NC20)* J7(NC21)* J8(NC22)* J9(NC23)* J17(DNU5)* J24(DNU4)* J27(NC24)* K9(NC18)* K27(NC19)* L10(NC16)* L26(NC17)*; U18 1(NC1)* 2(NC2)* 8(NC3)* 15(NC4)* 16(NC5)*; U21 9(NC1)* 21(NC2)* 24(NC3)* 25(NC4)* 28(NC5)*; U24 27(NC)* 52(NC)*; U25 23(CLKOUT)*; U40 16(PGOOD1)* 18(NC)* 32(CLKOUT)* 33(PHSASMD)* 34(MODE/PLLIN)*; U41 5(NC)*; U44 5(NC)*; U46 5(NC)*

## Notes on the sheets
sheet 22
- Power - Cyclone V GT Power
- (2.5V)
- 20mm Coin Cell
sheet 23
- Power 1 - DC Input & 12V, 3.3V Output
- 19V
  DC Input
- This should be a copper
  pour not a trace.
- POWER LED
sheet 24
- Power 2 - 1.1V (C5_VCC)
- CAD Note:
  Regulator input caps
  Place near regulator controller
- FSW = 350kHz
sheet 25
- Power 3 - 1.2V (C5 GTB)
- CAD Note:
  Regulator input caps
  Place near regulator controller
- Design Note:
  Prefer 0603 size cap
  25V rated voltage is sufficient
- Design Note:
  tss = Css x 0.6V/2uA
  Ramp rate ~990us
- Cad Note:
  Place output caps
  near inductor
- Design Note:
  Ith is tied to INTVCC for
  internal compensation
  CAD Note:
  Overlap R?? & R??
  pads at 1 of the pins
  Place resistor & cap
  near pin 6
sheet 26
- Power 4 - 2.5V (C5 2.5V), 1.8V & 5.0V
- Cad Note:
  Place capacitors
  near PVIN pins
- Cad Note:
  Place capacitors
  near inductor
- Design Note:
  Ith is tied to INTVCC for
  internal compensation
